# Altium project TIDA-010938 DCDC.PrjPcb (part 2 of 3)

## Sheet TIDA-010938 bidirectional DC-DC_Interleaved1.SchDoc
size 558 x 431 mm; Date: Not shown in title block; ApprovedBy: Not shown in title block; CheckedBy: Not shown in title block; Author: Not shown in title block; CompanyName: Not shown in title block; Engineer: Not shown in title block; Organization: Not shown in title block; Address1: Not shown in title block; Address2: Not shown in title block; Address3: Not shown in title block; Address4: Not shown in title block; DocumentNumber: 1; Revision: Use project parameter SCH_Rev; SheetNumber: 6; SheetTotal: 9; PageSetup: Record=PageOptions¦CenterHorizontal=True¦CenterVertical=True¦PrintScale=1.00¦XCorrection=1.00¦YCorrection=1.00¦PrintKind=0¦BorderSize=5000000¦LeftOffset=0¦BottomOffset=0¦Orientation=2¦PaperLength=1000¦PaperWidth=1000¦Scale=100¦PaperSource=15¦PrintQuality=600¦MediaType=1¦DitherType=10¦PaperKind=Letter¦PrintScaleMode=1
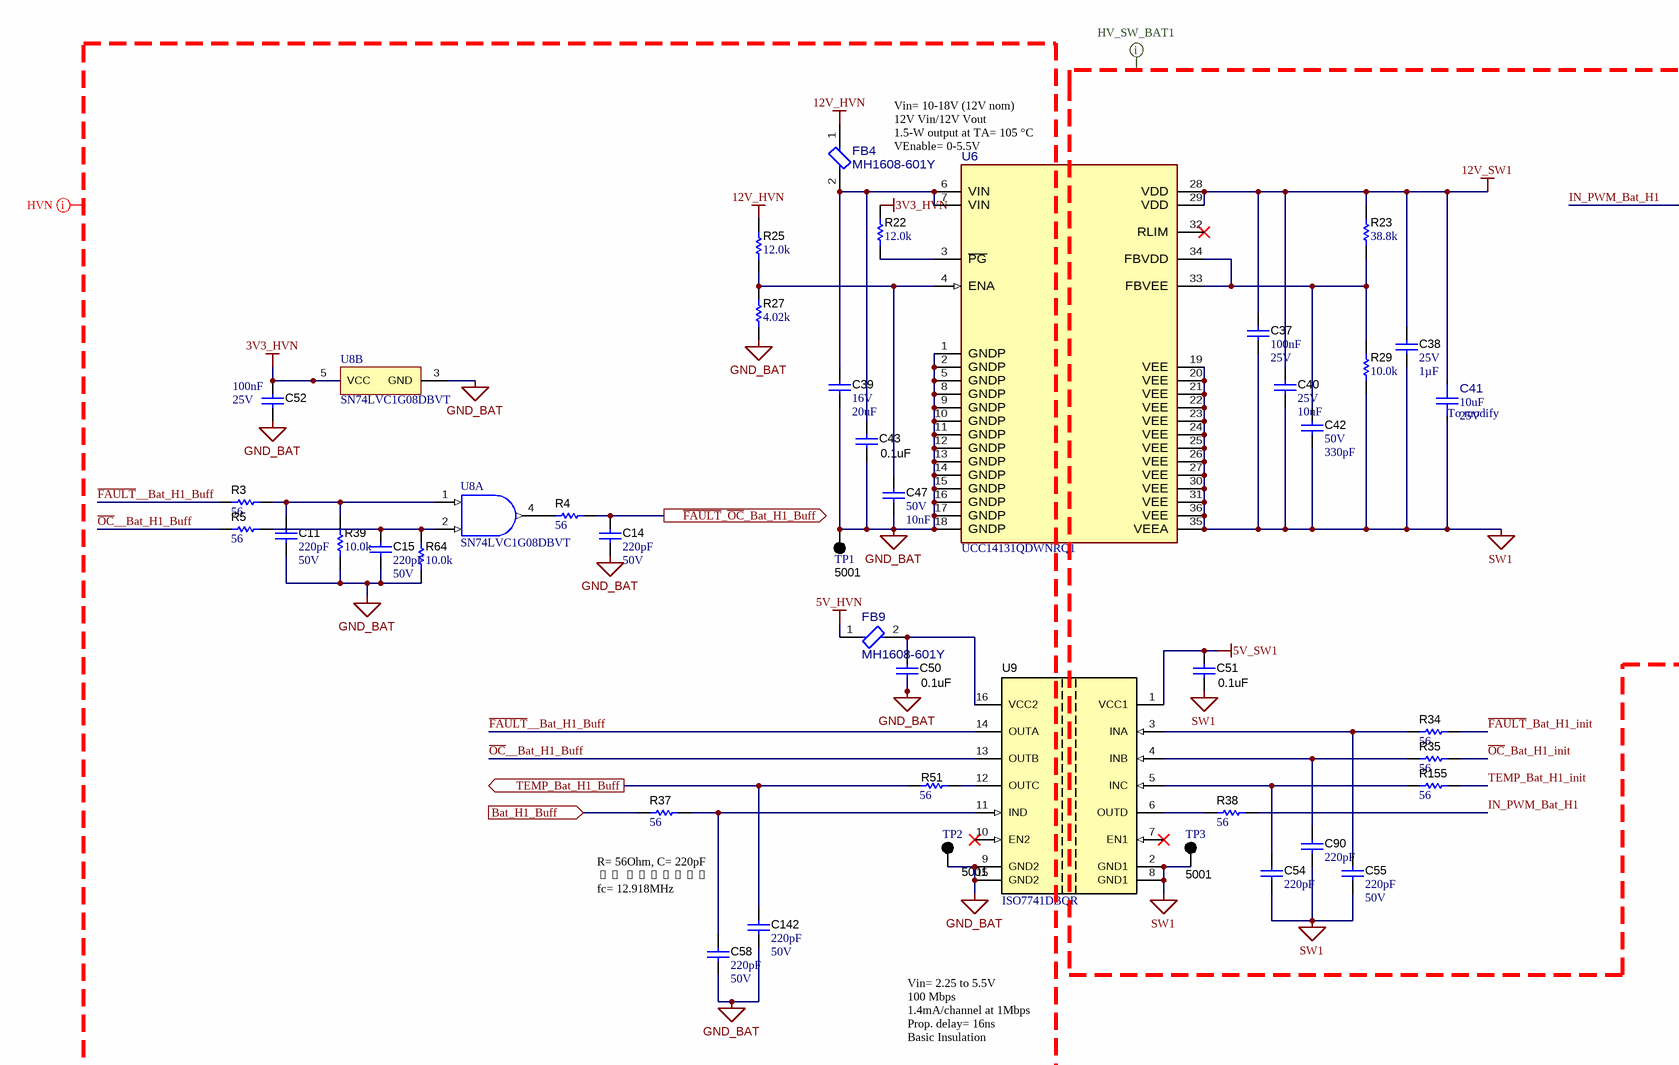
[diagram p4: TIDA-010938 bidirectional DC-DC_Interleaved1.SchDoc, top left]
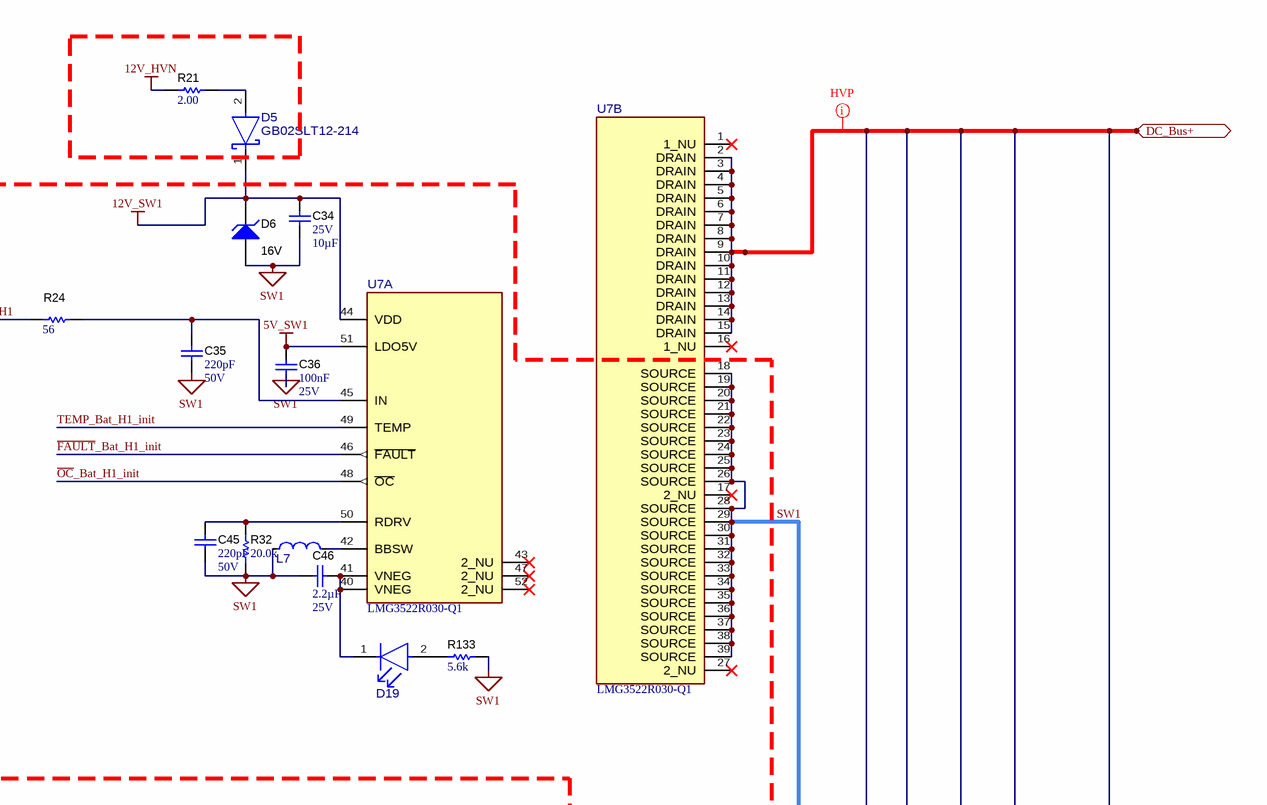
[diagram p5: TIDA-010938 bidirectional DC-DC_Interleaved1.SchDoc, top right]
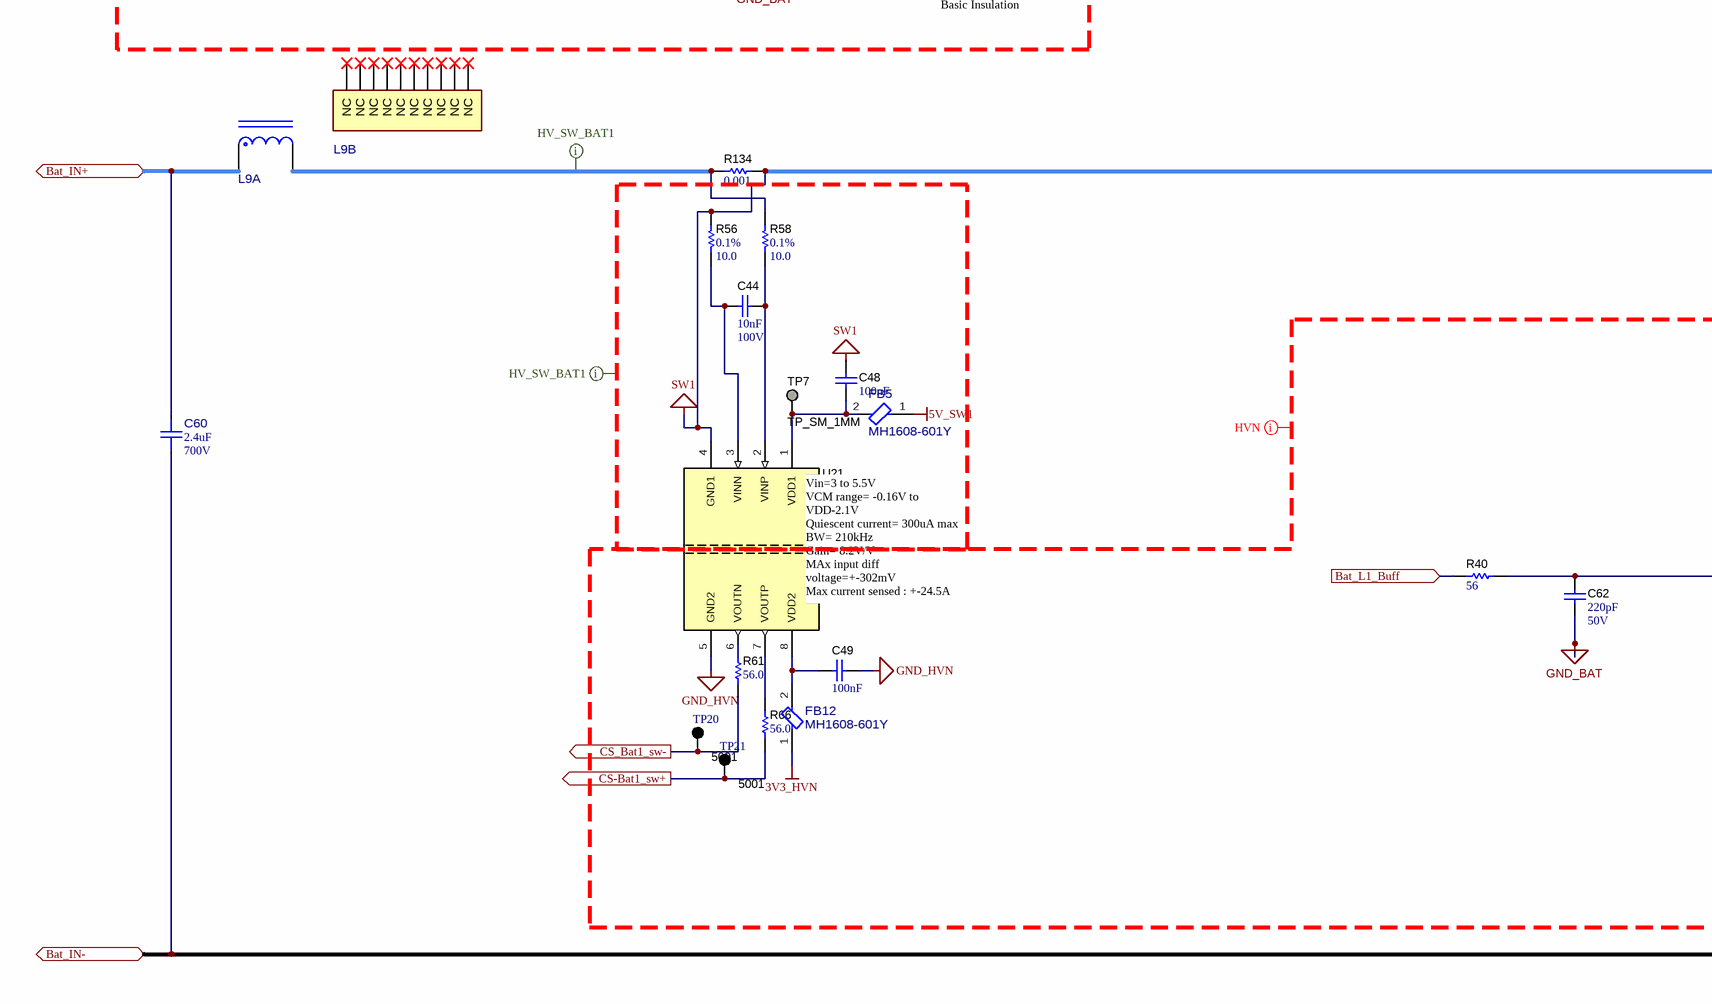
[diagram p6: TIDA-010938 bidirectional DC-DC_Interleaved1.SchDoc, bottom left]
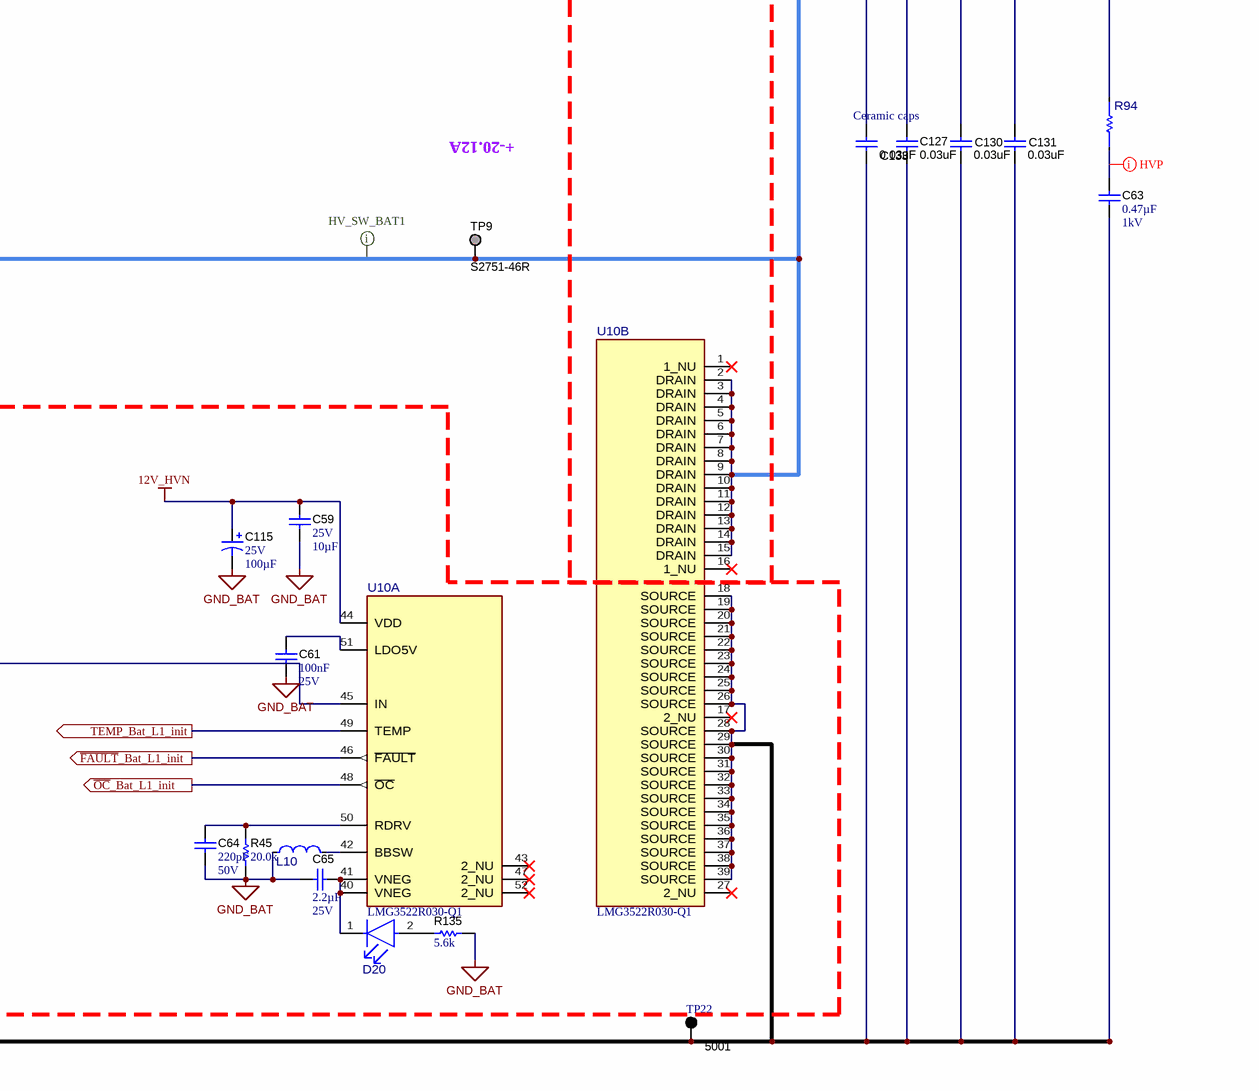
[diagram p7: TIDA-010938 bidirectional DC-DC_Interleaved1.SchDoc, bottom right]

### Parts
C11  Cap_F: 220pF  VDC_V: 50V  [0603]  (hidden comment: GRM188R71H221KA01D)
C14  Cap_F: 220pF  VDC_V: 50V  [0603]  (hidden comment: GRM188R71H221KA01D)
C15  Cap_F: 220pF  VDC_V: 50V  [0603]  (hidden comment: GRM188R71H221KA01D)
C34  VDC_V: 25V  ValueDisplayed: 10µF  [1206_180]  (hidden comment: TMK316AB7106KLHT)
C35  Cap_F: 220pF  VDC_V: 50V  [0603]  (hidden comment: GRM188R71H221KA01D)
C36  Cap_F: 100nF  VDC_V: 25V  [0603]  (hidden comment: 06033C104JAT2A)
C37  Cap_F: 100nF  VDC_V: 25V  [0603]  (hidden comment: 06033C104JAT2A)
C38  VDC_V: 25V  ValueDisplayed: 1µF  [0603]  (hidden comment: TMK107BJ105KA-T)
C39  VDC_V: 16V  ValueDisplayed: 20uF  [0704]  (hidden comment: GRMJN7R61C206ME05)
C40  VDC_V: 25V  ValueDisplayed: 10uF  [0603]  (hidden comment: TMK107BBJ106MA-T)
C41  ValueDisplayed: 10uF  VDC_V: 25V  [FP-ZRB18AR61E106ME01L_0603-MFG]  (hidden comment: ZRB18AR61E106ME01L)
C42  VDC_V: 50V  ValueDisplayed: 330pF  [0603]  (hidden comment: GRM1885C1H331JA01D)
C43  ValueDisplayed: 0.1uF  [0603]  (hidden comment: 885012206095)
C44  Cap_F: 10nF  VDC_V: 100V  [0603]  (hidden comment: CGA3E2X7R2A103K080AA)
C45  Cap_F: 220pF  VDC_V: 50V  [0603]  (hidden comment: GRM188R71H221KA01D)
C46  Cap_F: 2.2µF  VDC_V: 25V  [0805_HV]  (hidden comment: CGA4J3X7R1E225K125AB)
C47  VDC_V: 50V  Cap_F: 10nF  [0603]  (hidden comment: 885012206089)
C48  Cap_F: 100nF  [0603]  (hidden comment: 06033C104JAT2A)
C49  Cap_F: 100nF  [0603]  (hidden comment: 06033C104JAT2A)
C50  ValueDisplayed: 0.1uF  [0603]  (hidden comment: 885012206095)
C51  ValueDisplayed: 0.1uF  [0603]  (hidden comment: 885012206095)
C52  Cap_F: 100nF  VDC_V: 25V  [0603]  (hidden comment: 06033C104JAT2A)
C54  Cap_F: 220pF  [0603]  (hidden comment: GRM188R71H221KA01D)
C55  Cap_F: 220pF  VDC_V: 50V  [0603]  (hidden comment: GRM188R71H221KA01D)
C58  Cap_F: 220pF  VDC_V: 50V  [0603]  (hidden comment: GRM188R71H221KA01D)
C59  VDC_V: 25V  ValueDisplayed: 10µF  [1206_180]  (hidden comment: TMK316AB7106KLHT)
C60  ValueDisplayed: 2.4uF  VDC_V: 700V  [FP-C4AUJBU4240M1WJ_RADIAL-MFG]  (hidden comment: C4AUJBU4240M1WJ)
C61  Cap_F: 100nF  VDC_V: 25V  [0603]  (hidden comment: 06033C104JAT2A)
C62  Cap_F: 220pF  VDC_V: 50V  [0603]  (hidden comment: GRM188R71H221KA01D)
C63  ValueDisplayed: 0.47µF  VDC_V: 1kV  [2220]  (hidden comment: 2220Y1K00474KETWS2)
C64  Cap_F: 220pF  VDC_V: 50V  [0603]  (hidden comment: GRM188R71H221KA01D)
C65  Cap_F: 2.2µF  VDC_V: 25V  [0805_HV]  (hidden comment: CGA4J3X7R1E225K125AB)
C90  Cap_F: 220pF  [0603]  (hidden comment: GRM188R71H221KA01D)
C115  VDC_V: 25V  ValueDisplayed: 100µF  [UWT_630x770]  (hidden comment: UWT1E101MCL1GS)
C127  ValueDisplayed: 0.03uF  [1812_254]  (hidden comment: C1812C303KDGLCAUTO)
C130  ValueDisplayed: 0.03uF  [1812_254]  (hidden comment: C1812C303KDGLCAUTO)
C131  ValueDisplayed: 0.03uF  [1812_254]  (hidden comment: C1812C303KDGLCAUTO)
C133  ValueDisplayed: 0.03uF  [1812_254]  (hidden comment: C1812C303KDGLCAUTO)
C142  Cap_F: 220pF  VDC_V: 50V  [0603]  (hidden comment: GRM188R71H221KA01D)
D5  GB02SLT12-214  [FP-GB02SLT12-214_DO-214AA-MFG]
D6  value 16V  [SOD-123]  (hidden comment: BZT52C16-7-F)
D19  KG DELLS1.22-JGKH-24  [FP-KG DELLS1.22-JGKH-24_0603-MFG]  (value not drawn)
D20  KG DELLS1.22-JGKH-24  [FP-KG DELLS1.22-JGKH-24_0603-MFG]  (value not drawn)
FB4  MH1608-601Y  [FP-MH1608-601Y_0603-MFG]
FB5  MH1608-601Y  [FP-MH1608-601Y_0603-MFG]
FB9  MH1608-601Y  [FP-MH1608-601Y_0603-MFG]
FB12  MH1608-601Y  [FP-MH1608-601Y_0603-MFG]
L7  SDEM20161T-4R7MS  [FP-SDEM20161T-4R7MS_SMD2-MFG]  (value not drawn)
L9  B180975  [FP-B180975_PTH12_55MM5_50MM0-MFG]  (value not drawn)  (parts A,B of 2)
L10  SDEM20161T-4R7MS  [FP-SDEM20161T-4R7MS_SMD2-MFG]  (value not drawn)
R3  ValueDisplayed: 56  [0603]  (hidden comment: RG1608P-560-B-T5)
R4  ValueDisplayed: 56  [0603]  (hidden comment: RG1608P-560-B-T5)
R5  ValueDisplayed: 56  [0603]  (hidden comment: RG1608P-560-B-T5)
R21  ValueDisplayed: 2.00  [0603]  (hidden comment: RT0603DRE072RL)
R22  ValueDisplayed: 12.0k  [0603]  (hidden comment: ERJ-3EKF1202V)
R23  ValueDisplayed: 38.8k  [0603]  (hidden comment: RT0603DRE0738K8L)
R24  ValueDisplayed: 56  [0603]  (hidden comment: RG1608P-560-B-T5)
R25  ValueDisplayed: 12.0k  [0603]  (hidden comment: ERJ-3EKF1202V)
R27  ValueDisplayed: 4.02k  [0603]  (hidden comment: RT0603BRD074K02L)
R29  ValueDisplayed: 10.0k  [0603]  (hidden comment: RG1608P-103-B-T5)
R32  ValueDisplayed: 20.0k  [0603]  (hidden comment: RC0603FR-0720KL)
R34  ValueDisplayed: 56  [0603]  (hidden comment: RG1608P-560-B-T5)
R35  ValueDisplayed: 56  [0603]  (hidden comment: RG1608P-560-B-T5)
R37  ValueDisplayed: 56  [0603]  (hidden comment: RG1608P-560-B-T5)
R38  ValueDisplayed: 56  [0603]  (hidden comment: RG1608P-560-B-T5)
R39  ValueDisplayed: 10.0k  [0603]  (hidden comment: RG1608P-103-B-T5)
R40  ValueDisplayed: 56  [0603]  (hidden comment: RG1608P-560-B-T5)
R45  ValueDisplayed: 20.0k  [0603]  (hidden comment: RC0603FR-0720KL)
R51  ValueDisplayed: 56  [0603]  (hidden comment: RG1608P-560-B-T5)
R56  Tolerance_%: 0.1%  ValueDisplayed: 10.0  [0603]  (hidden comment: RT0603BRD0710RL)
R58  Tolerance_%: 0.1%  ValueDisplayed: 10.0  [0603]  (hidden comment: RT0603BRD0710RL)
R61  ValueDisplayed: 56.0  [0603]  (hidden comment: RC0603FR-0756RL)
R64  ValueDisplayed: 10.0k  [0603]  (hidden comment: RG1608P-103-B-T5)
R66  ValueDisplayed: 56.0  [0603]  (hidden comment: RC0603FR-0756RL)
R94  CSR0805FKR250  [FP-CSR0805FKR250_0805-MFG]  (value not drawn)
R133  ValueDisplayed: 5.6k  [0603]  (hidden comment: RC0603JR-075K6L)
R134  ValueDisplayed: 0.001  [CSS2H-2512_H077Y042]  (hidden comment: CSS2H-2512R-1L00F)
R135  ValueDisplayed: 5.6k  [0603]  (hidden comment: RC0603JR-075K6L)
R155  ValueDisplayed: 56  [0603]  (hidden comment: RG1608P-560-B-T5)
TP1  5001  [Keystone5001]
TP2  5001  [Keystone5001]
TP3  5001  [Keystone5001]
TP7  TP_SM_1MM  [TP_SM_1MM]  (no BOM)
TP9  S2751-46R  [Harwin_S2751-46R]  (no BOM)
TP20  5001  [Keystone5001]
TP21  5001  [Keystone5001]
TP22  5001  [Keystone5001]
U6  UCC14131QDWNRQ1  [DWJ0036A-MFG]
U7  LMG3522R030-Q1  [RQS0052C-C01-MFG]  (parts A,B of 2)
U8  SN74LVC1G08DBVT  [DBV0005A_N]  (parts A,B of 2)
U9  ISO7741DBQR  [DBQ0016A_N]
U10  LMG3522R030-Q1  [RQS0052C-C01-MFG]  (parts A,B of 2)
U21  AMC1302DWV  [DWV0008A]

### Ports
Bat_H1_Buff (in), Bat_IN+ (bidir), Bat_IN- (bidir), Bat_L1_Buff (in), CS-Bat1_sw+ (out), CS_Bat1_sw- (out), DC_Bus+ (bidir), TEMP_Bat_H1_Buff (out), TEMP_Bat_L1_init (out), ~{FAULT}_Bat_L1_init (out), ~{FAULT}_~{OC}_Bat_H1_Buff (out), ~{OC}_Bat_L1_init (out)

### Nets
3V3_HVN: C52.1 FB12.1 R22.1 U8.5(VCC)
5V_HVN: FB9.1
5V_SW1: C36.2 C51.1 FB5.1 U7.51(LDO5V) U9.1(VCC1)
12V_HVN: C59.1 C115.1(+) FB4.1 R21.1 R25.1 U10.44(VDD)
12V_SW1: C34.1 C37.2 C38.2 C40.2 C41.1 D5.1(CATHODE) D6.1(K) R23.1 U6.28(VDD) U6.29(VDD) U7.44(VDD)
DC_Bus-: C60.1 C63.2 C127.2 C130.2 C131.2 C133.2 TP22.1 U10.18(SOURCE) U10.19(SOURCE) U10.20(SOURCE) U10.21(SOURCE) U10.22(SOURCE) U10.23(SOURCE) U10.24(SOURCE) U10.25(SOURCE) U10.26(SOURCE) U10.28(SOURCE) U10.29(SOURCE) U10.30(SOURCE) U10.31(SOURCE) U10.32(SOURCE) U10.33(SOURCE) U10.34(SOURCE) U10.35(SOURCE) U10.36(SOURCE) U10.37(SOURCE) U10.38(SOURCE) U10.39(SOURCE) ; port Bat_IN-
GND_BAT: C11.1 C14.1 C15.1 C39.1 C43.2 C47.1 C50.2 C52.2 C58.1 C59.2 C61.1 C62.1 C64.1 C65.2 C115.2(-) C142.1 L10.1 R27.1 R39.1 R45.1 R64.1 R135.1 TP1.1 TP2.1 U6.1(GNDP) U6.2(GNDP) U6.5(GNDP) U6.8(GNDP) U6.9(GNDP) U6.10(GNDP) U6.11(GNDP) U6.12(GNDP) U6.13(GNDP) U6.14(GNDP) U6.15(GNDP) U6.16(GNDP) U6.17(GNDP) U6.18(GNDP) U8.3(GND) U9.9(GND2) U9.15(GND2)
GND_HVN: C49.2 U21.5(GND2)
SW1: C34.2 C35.1 C36.1 C37.1 C38.1 C40.1 C41.2 C42.2 C45.1 C46.2 C48.2 C51.2 C54.1 C55.1 C90.1 D6.2(A) L7.1 R29.2 R32.1 R56.1 R133.1 R134.2 TP3.1 TP9.1 U6.19(VEE) U6.20(VEE) U6.21(VEE) U6.22(VEE) U6.23(VEE) U6.24(VEE) U6.25(VEE) U6.26(VEE) U6.27(VEE) U6.30(VEE) U6.31(VEE) U6.35(VEEA) U6.36(VEE) U7.18(SOURCE) U7.19(SOURCE) U7.20(SOURCE) U7.21(SOURCE) U7.22(SOURCE) U7.23(SOURCE) U7.24(SOURCE) U7.25(SOURCE) U7.26(SOURCE) U7.28(SOURCE) U7.29(SOURCE) U7.30(SOURCE) U7.31(SOURCE) U7.32(SOURCE) U7.33(SOURCE) U7.34(SOURCE) U7.35(SOURCE) U7.36(SOURCE) U7.37(SOURCE) U7.38(SOURCE) U7.39(SOURCE) U9.2(GND1) U9.8(GND1) U10.2(DRAIN) U10.3(DRAIN) U10.4(DRAIN) U10.5(DRAIN) U10.6(DRAIN) U10.7(DRAIN) U10.8(DRAIN) U10.9(DRAIN) U10.10(DRAIN) U10.11(DRAIN) U10.12(DRAIN) U10.13(DRAIN) U10.14(DRAIN) U10.15(DRAIN) U21.4(GND1)
Bat_H1_Buff: R37.1 ; port Bat_H1_Buff
Bat_IN+: C60.2 L9.1 ; port Bat_IN+
Bat_L1_Buff: R40.1 ; port Bat_L1_Buff
CS-Bat1_sw+: R66.1 TP21.1 ; port CS-Bat1_sw+
CS_Bat1_sw-: R61.1 TP20.1 ; port CS_Bat1_sw-
DC_Bus+: C127.1 C130.1 C131.1 C133.1 R94.2 U7.2(DRAIN) U7.3(DRAIN) U7.4(DRAIN) U7.5(DRAIN) U7.6(DRAIN) U7.7(DRAIN) U7.8(DRAIN) U7.9(DRAIN) U7.10(DRAIN) U7.11(DRAIN) U7.12(DRAIN) U7.13(DRAIN) U7.14(DRAIN) U7.15(DRAIN) ; port DC_Bus+
~{FAULT}__Bat_H1_Buff: R3.1 U9.14(OUTA)
~{FAULT}_Bat_H1_init: R34.2 U7.46(~{FAULT})
~{FAULT}_Bat_L1_init: U10.46(~{FAULT}) ; port ~{FAULT}_Bat_L1_init
~{FAULT}_~{OC}_Bat_H1_Buff: C14.2 R4.2 ; port ~{FAULT}_~{OC}_Bat_H1_Buff
IN_PWM_Bat_H1: R24.1 R38.2
~{OC}__Bat_H1_Buff: R5.1 U9.13(OUTB)
~{OC}_Bat_H1_init: R35.2 U7.48(~{OC})
~{OC}_Bat_L1_init: U10.48(~{OC}) ; port ~{OC}_Bat_L1_init
TEMP_Bat_H1_Buff: C142.2 R51.1 ; port TEMP_Bat_H1_Buff
TEMP_Bat_H1_init: R155.2 U7.49(TEMP)
TEMP_Bat_L1_init: U10.49(TEMP) ; port TEMP_Bat_L1_init
NetC11_2: C11.2 R3.2 R39.2 U8.1(A)
NetC15_2: C15.2 R5.2 R64.2 U8.2(B)
NetC35_2: C35.2 R24.2 U7.45(IN)
NetC39_2: C39.2 C43.1 FB4.2 U6.6(VIN) U6.7(VIN)
NetC42_1: C42.1 R23.2 R29.1 U6.33(FBVEE) U6.34(FBVDD)
NetC44_1: C44.1 R58.2 U21.2(VINP)
NetC44_2: C44.2 R56.2 U21.3(VINN)
NetC45_2: C45.2 R32.2 U7.50(RDRV)
NetC46_1: C46.1 D19.1(CATHODE) U7.40(VNEG) U7.41(VNEG)
NetC47_2: C47.2 R25.2 R27.2 U6.4(ENA)
NetC48_1: C48.1 FB5.2 TP7.1 U21.1(VDD1)
NetC49_1: C49.1 FB12.2 U21.8(VDD2)
NetC50_1: C50.1 FB9.2 U9.16(VCC2)
NetC54_2: C54.2 R155.1 U9.5(INC)
NetC55_2: C55.2 R34.1 U9.3(INA)
NetC58_2: C58.2 R37.2 U9.11(IND)
NetC61_2: C61.2 U10.51(LDO5V)
NetC62_2: C62.2 R40.2 U10.45(IN)
NetC63_1: C63.1 R94.1
NetC64_2: C64.2 R45.2 U10.50(RDRV)
NetC65_1: C65.1 D20.1(CATHODE) U10.40(VNEG) U10.41(VNEG)
NetC90_2: C90.2 R35.1 U9.4(INB)
NetD5_2: D5.2(ANODE) R21.2
NetD19_2: D19.2(ANODE) R133.2
NetD20_2: D20.2(ANODE) R135.2
NetL7_2: L7.2 U7.42(BBSW)
NetL9_6: L9.6 R58.1 R134.1
NetL10_2: L10.2 U10.42(BBSW)
NetR4_1: R4.1 U8.4(Y)
NetR22_2: R22.2 U6.3(~{PG})
NetR38_1: R38.1 U9.6(OUTD)
NetR51_2: R51.2 U9.12(OUTC)
NetR61_2: R61.2 U21.6(VOUTN)
NetR66_2: R66.2 U21.7(VOUTP)

Not connected (* = marked no-connect by the designer): L9 2(NC)* 3(NC)* 4(NC)* 5(NC)* 7(NC)* 8(NC)* 9(NC)* 10(NC)* 11(NC)* 12(NC)*; U6 32(RLIM)*; U7 1(1_NU)* 16(1_NU)* 17(2_NU)* 27(2_NU)* 43(2_NU)* 47(2_NU)* 52(2_NU)*; U9 7(EN1)* 10(EN2)*; U10 1(1_NU)* 16(1_NU)* 17(2_NU)* 27(2_NU)* 43(2_NU)* 47(2_NU)* 52(2_NU)*

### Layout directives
net class HVN: 3V3_HVN, 5V_HVN, 5V_SW1, 12V_HVN, 12V_SW1, GND_BAT, IN_PWM_Bat_H1, SW1, TEMP_Bat_H1_init, ~{FAULT}__Bat_H1_Buff, ~{FAULT}_Bat_H1_init, ~{OC}__Bat_H1_Buff, ~{OC}_Bat_H1_init
net class HV_SW_BAT1: 3V3_HVN, 5V_SW1, 12V_HVN, 12V_SW1, GND_BAT, GND_HVN, IN_PWM_Bat_H1, NetL9_6, SW1, TEMP_Bat_H1_init, ~{FAULT}_Bat_H1_init, ~{OC}_Bat_H1_init
net class HVP: DC_Bus+, NetC63_1

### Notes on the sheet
- Vin= 10-18V (12V nom)
  12V Vin/12V Vout
  1.5-W output at TA= 105 °C
  VEnable= 0-5.5V
- (near C41) To modify
- R= 56Ohm, C= 220pF
  𝜏= 1.23e-8
  fc= 12.918MHz
- Vin= 2.25 to 5.5V
  100 Mbps
  1.4mA/channel at 1Mbps
  Prop. delay= 16ns
  Basic Insulation
- +-20.12A
- Ceramic caps
- (near U21) 9 mA @ 5V
- (near U21) Vin=3 to 5.5V
  VCM range= -0.16V to VDD-2.1V
  Quiescent current= 300uA max
  BW= 210kHz
  Gain= 8.2V/V
  MAx input diff voltage=+-302mV
  Max current sensed : +-24.5A
- (near U21) 10 mA @ 5V

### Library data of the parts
C11 C14 C15 C35 C45 C55 C58 C62 C64 C142 = CMP-0007442-5: CAP, CERM, 220 pF, 50 V, +/- 10%, X7R, 0603; Manufacturer: MuRata; TaMin_C: -55°C; Polarized: N; SizeAreaWB_mm2: 4.68; Value1: Unknown; U/M: EA; Value: 220pF; TaMax_C: 125°C; SizeZ_mm: 1; SizeX_mm: 1.6; SizeY_mm: 0.8; SizeArea_mm2: 1.28; AEC Category: Q200
C34 C59 = CMP-0750154-1: CAP, CERM, 10 µF, 25 V,+/- 10%, X7R, AEC-Q200 Grade 1, 1206; Manufacturer: Taiyo Yuden; AEC Qualified: Y; SizeZ_mm: 1.8; TaMax_C: 125°C; TaMin_C: -55°C; Cap_Case: 1206; Polarized: N; AEC Grade: 1; SizeY_mm: 1.6; Value: 10uF; SizeX_mm: 3.2; SizeAreaWB_mm2: 10.92; AEC Category: Q200; U/M: EA; SizeArea_mm2: 5.12
C36 C37 C52 C61 = CMP-0006752-5: CAP, CERM, 0.1 uF, 25 V, +/- 5%, X7R, 0603; Manufacturer: AVX; TaMin_C: -55°C; ESR_ohm: 0.05; Polarized: N; SizeAreaWB_mm2: 4.68; Value1: 0.05 ohm; U/M: EA; Value: 0.1uF; TaMax_C: 125°C; SizeZ_mm: 1; SizeX_mm: 1.6; SizeY_mm: 0.8; SizeArea_mm2: 1.28; AEC Category: Q200
C38 = CMP-0086152-1: CAP, CERM, 1 µF, 25 V,+/- 10%, X5R, 0603; Manufacturer: Taiyo Yuden; SizeAreaWB_mm2: 4.68; SizeZ_mm: 1; U/M: EA; Green_REACh: Passed; Value: 1uF; AEC Qualified: N; TaMax_C: 85°C; Green_Lifecycle: Active; AEC Category: Q200; SizeArea_mm2: 1.28; TaMin_C: -55°C; SizeY_mm: 0.8; SizeX_mm: 1.6
C39 = CMP-0009474-2: CAP, CERM, 20 uF, 16 V, +/- 20%, X5R, 0704; Manufacturer: MuRata; TaMin_C: -55°C; Polarized: N; SizeAreaWB_mm2: 5.6; Value1: Unknown; U/M: EA; Value: 20uF; TaMax_C: 85°C; SizeZ_mm: 0.8; SizeX_mm: 1; SizeY_mm: 1.8; Cap_F: 20µF; AEC Category: Q200
C40 = CMP-0007507-5: CAP, CERM, 10 uF, 25 V, +/- 20%, X5R, 0603; Manufacturer: Taiyo Yuden; TaMin_C: -55°C; Polarized: N; SizeAreaWB_mm2: 4.68; Value1: Unknown; U/M: EA; Value: 10uF; TaMax_C: 85°C; SizeZ_mm: 1; SizeX_mm: 1.6; SizeY_mm: 0.8; SizeArea_mm2: 1.28; Cap_F: 10µF; AEC Category: Q200
C41 = CMP-0094458-1: 10µF ±20% 25V Ceramic Capacitor X5R 0603 (1608 Metric); Manufacturer: Murata Electronics; SizeZ_mm: 1.2mm; AEC Qualified: No
C42 = CMP-0007209-4: CAP, CERM, 330 pF, 50 V, +/- 5%, C0G/NP0, 0603; Manufacturer: MuRata; TaMin_C: -55°C; Polarized: N; SizeAreaWB_mm2: 4.68; Value1: Unknown; U/M: EA; Value: 330pF; TaMax_C: 125°C; SizeZ_mm: 1; SizeX_mm: 1.6; SizeY_mm: 0.8; SizeArea_mm2: 1.28; AEC Category: Q200
C43 C50 C51 = CMP-0006837-4: CAP, CERM, 0.1 uF, 50 V, +/- 10%, X7R, 0603; Manufacturer: Wurth Elektronik; TaMin_C: -55°C; Polarized: N; SizeAreaWB_mm2: 4.68; Value1: Unknown; U/M: EA; Value: 0.1uF; TaMax_C: 125°C; SizeZ_mm: 1; SizeX_mm: 1.6; SizeY_mm: 0.8; Value2: 50V; SizeArea_mm2: 1.28; CompType: Capacitor; Cap_F: 100nF; AEC Category: Q200
C44 = CMP-0007082-4: CAP, CERM, 0.01 uF, 100 V, +/- 10%, X7R, AEC-Q200 Grade 1, 0603; Manufacturer: TDK; TaMin_C: -55°C; ESR_ohm: 2.35428d; Polarized: N; SizeAreaWB_mm2: 4.68; Value1: 0.235428 ohm; U/M: EA; Value: 0.01uF; TaMax_C: 125°C; SizeZ_mm: 1; SizeX_mm: 1.6; SizeY_mm: 0.8; SizeArea_mm2: 1.28; AEC Qualified: Y; IRMS_A: 3.96995dA; AEC Category: Q200
C46 C65 = CMP-0007975-2: CAP, CERM, 2.2 uF, 25 V, +/- 10%, X7R, AEC-Q200 Grade 1, 0805; Manufacturer: TDK; TaMin_C: -55°C; Polarized: N; SizeAreaWB_mm2: 6.75; Value1: Unknown; U/M: EA; Value: 2.2uF; TaMax_C: 125°C; SizeZ_mm: 1.45; SizeX_mm: 2; SizeY_mm: 1.25; Cap_Case: 0805; SizeArea_mm2: 2.5; AEC Qualified: Y; AEC Grade: 1; AEC Category: Q200
C47 = CMP-0750039-1: CAP, CERM, 0.01 µF, 50 V,+/- 10%, X7R, 0603; Manufacturer: Wurth Elektronik; Polarized: N; AEC Category: Q200; TaMax_C: 125°C; SizeAreaWB_mm2: 4.68; Value: 0.01uF; SizeArea_mm2: 1.28; SizeY_mm: 0.8; SizeZ_mm: 1; ValueDisplayed: 0.01µF; SizeX_mm: 1.6; U/M: EA; TaMin_C: -55°C
C48 C49 = CMP-0006752-5: CAP, CERM, 0.1 uF, 25 V, +/- 5%, X7R, 0603; Manufacturer: AVX; TaMin_C: -55°C; ESR_ohm: 0.05; Polarized: N; SizeAreaWB_mm2: 4.68; Value1: 0.05 ohm; U/M: EA; Value: 0.1uF; TaMax_C: 125°C; SizeZ_mm: 1; SizeX_mm: 1.6; SizeY_mm: 0.8; Value2: 25V; SizeArea_mm2: 1.28; AEC Category: Q200
C54 C90 = CMP-0007442-5: CAP, CERM, 220 pF, 50 V, +/- 10%, X7R, 0603; Manufacturer: MuRata; TaMin_C: -55°C; Polarized: N; SizeAreaWB_mm2: 4.68; Value1: Unknown; U/M: EA; Value: 220pF; TaMax_C: 125°C; SizeZ_mm: 1; SizeX_mm: 1.6; SizeY_mm: 0.8; Value2: 50V; SizeArea_mm2: 1.28; AEC Category: Q200
C60 = CMP-0045063-1: 2.4 µF Film Capacitor 700V Polypropylene (PP), Metallized Radial; Manufacturer: KEMET; AEC Grade: Grade 2; AEC Qualified: Yes; Cap_F: 2.4µF; SizeZ_mm: 20.7mm; Tolerance_%: 5%; Value: 2.4µF
C63 = CMP-0086177-1: CAP, CERM, 0.47 µF, 1000 V,+/- 10%, X7R, AEC-Q200 Grade 1, 2220; Manufacturer: Knowles Capacitors; SizeAreaWB_mm2: 53.9; AEC Category: Q200; TaMax_C: 125°C; SizeArea_mm2: 28.5; SizeX_mm: 5.7; SizeZ_mm: 1.35; Value: 0.47uF; AEC Qualified: Y; TaMin_C: -55°C; SizeY_mm: 5; Value2: 1000V; AEC Grade: 1; U/M: EA; Cap_F: 470nF; Polarized: N
C115 = CMP-0081462-1: CAP, AL, 100 µF, 25 V, +/- 20%, SMD; Manufacturer: Nichicon; TaMin_C: -55°C; Polarized: Y; SizeAreaWB_mm2: 77.4; U/M: EA; Value: 100uF; TaMax_C: 105°C; SizeZ_mm: 8; SizeX_mm: 7; SizeY_mm: 6.6; Cap_Case: 6.3x7.7mm; SizeArea_mm2: 46.2; CompType: Capacitor; AEC Qualified: N; IRMS_A: 91mA; AEC Category: Q200
C127 C130 C131 C133 = CMP-0009326-2: 0.03 µF ±10% 1000V (1kV) Ceramic Capacitor C0G, NP0 1812 (4532 Metric); Manufacturer: Kemet; Polarized: N; Value: 0.03uF; U/M: EA; Cap_F: 30nF; Value1: Unknown; TaMin_C: -55°C; TaMax_C: 125°C; Cap_Case: 1812; AEC Category: Q200; SizeArea_mm2: 14.4; SizeAreaWB_mm2: 23.1; SizeX_mm: 4.5; SizeY_mm: 3.2; SizeZ_mm: 2.54
D5 = CMP-0095009-1: Diode Silicon Carbide Schottky 1200 V 2A (DC) Surface Mount DO-214AA; Manufacturer: GeneSiC Semiconductor; Max Surge Forward Current: 20A; ValueDisplayed: 122pF; Vf_V: 1.2kV; Peak Reverse Current: 1uA; SizeZ_mm: 2.44mm; AEC Qualified: No; TJmax_C: 175°C
D6 = CMP-0005769-4: Diode, Zener, 16 V, 500 mW, AEC-Q101, SOD-123; Manufacturer: Diodes Inc.; SizeZ_mm: 1.35; AEC Qualified: Y; SizeX_mm: 3.85; AEC Category: Q101; Power_W: 500mW; SizeY_mm: 1.7; Value1: 0.5W; SizeAreaWB_mm2: 13.095; SizeArea_mm2: 6.545; RJA_CperW: 338
D19 D20 = CMP-0093310-1: Standard LEDs - SMD Green TOPLED E 1608; Manufacturer: Osram Opto; AEC Grade: Grade 2; LambdaP: 572nm; SizeZ_mm: 0.7mm; LuminousFlux_PhiV: 0.016-0.0295lm; Luminous Intensity: 4.5-9.7mcd; LambdaD: 570nm; Tjmax_C: 125°C; Angle: 120°; Led Orientation: Top View; Forward Current: 2mA; Vf_V: 1.8V; AEC Qualified: Yes; Vr_V: 12V
FB4 FB5 FB9 FB12 = CMP-0037505-1: 600 Ohms @ 100 MHz 1 Power, Signal Line Ferrite Bead 0603 (1608 Metric) 1A 200mOhm; Manufacturer: Bourns; DCR_ohm: 0.2; SizeZ_mm: 1mm; AEC Qualified: No; Impedance At Frequency: 600Ω @ 100MHz; Test Frequency: 100MHz; Tolerance_%: 25%
L7 L10 = CMP-0089347-1: 4.7µH Unshielded Inductor 1.1A 426mOhm Max 0806 (2016 Metric); Manufacturer: Cyntec; AEC Qualified: No; Material: Metal Dust; Isat: 1.26A; Test Frequency: 1MHz; DCR_ohm: 0.426; SizeZ_mm: 1mm; Tolerance_%: 20%
L9 = CMP-0048784-1: Bi-directional DC-DC Inductor 186.7µH ± 10%; Manufacturer: Bourns; AEC Qualified: No; SizeZ_mm: 45mm; Value: 186.7uH; Test Frequency: 100kHz
R3-R5 R24 R34 R35 R37 R38 R40 R51 R155 = CMP-0023572-3: RES, 56, 0.1%, 0.1 W, 0603; Manufacturer: Susumu Co Ltd; Power_W: 100mW; TempCo: 25 ppm/C; Value_Code: 56R0; U/M: EA; Value: 56; SizeX_mm: 1.6; SizeY_mm: 0.8; SizeZ_mm: 1; Value2: 0.1W; SizeArea_mm2: 1.28; VDC_V: 75V; AEC Category: Q200
R21 = CMP-0025114-2: RES, 2.00, 0.5%, 0.1 W, 0603; Manufacturer: Yageo America; Power_W: 100mW; TempCo: 50 ppm/C; Value_Code: 2R00; U/M: EA; Value: 2.00; EIA_Code: E192; Res_ohm: 2; SizeX_mm: 1.6; SizeY_mm: 0.8; SizeZ_mm: 1; Value2: 0.1W; SizeArea_mm2: 1.28; VDC_V: 75V; AEC Category: Q200
R22 R25 = CMP-0022685-3: RES, 12.0 k, 1%, 0.1 W, 0603; Manufacturer: Panasonic; Power_W: 100mW; TempCo: 100 ppm/C; Value_Code: 12k0; U/M: EA; Value: 12.0k; Res_ohm: 12k; SizeX_mm: 1.6; SizeY_mm: 0.8; SizeZ_mm: 1; Value2: 0.1W; SizeArea_mm2: 1.28; VDC_V: 75V; AEC Category: Q200
R23 = CMP-0025200-2: RES, 38.8 k, 0.5%, 0.1 W, 0603; Manufacturer: Yageo America; Power_W: 100mW; TempCo: 50 ppm/C; Value_Code: 38k8; U/M: EA; Value: 38.8k; EIA_Code: E192; SizeX_mm: 1.6; SizeY_mm: 0.8; SizeZ_mm: 1; Value2: 0.1W; SizeArea_mm2: 1.28; VDC_V: 75V; AEC Category: Q200
R27 = CMP-0024286-2: RES, 4.02 k, 0.1%, 0.1 W, 0603; Manufacturer: Yageo America; Power_W: 100mW; TempCo: 25 ppm/C; Value_Code: 4k02; U/M: EA; Value: 4.02k; EIA_Code: E192; SizeX_mm: 1.6; SizeY_mm: 0.8; SizeZ_mm: 1; Value2: 0.1W; SizeArea_mm2: 1.28; VDC_V: 75V; AEC Category: Q200
R29 = CMP-0023404-1: RES, 10.0 k, 0.1%, 0.1 W, 0603; Manufacturer: Susumu Co Ltd; Power_W: 100mW; TempCo: 25 ppm/C; Value_Code: 10k0; U/M: EA; Value: 10.0k; EIA_Code: E192; Res_ohm: 10k; SizeX_mm: 1.6; SizeY_mm: 0.8; SizeZ_mm: 1; Value2: 0.1W; SizeArea_mm2: 1.28; VDC_V: 75V; AEC Category: Q200
R32 R45 = CMP-0022906-5: RES, 20.0 k, 1%, 0.1 W, 0603; Manufacturer: Yageo; Power_W: 100mW; TempCo: 100 ppm/C; Value_Code: 20k0; Value: 20.0k; EIA_Code: E96; Res_ohm: 20k; SizeX_mm: 1.6; SizeY_mm: 0.8; SizeZ_mm: 1; Value2: 0.1W; SizeArea_mm2: 1.28; AEC Qualified: N; VDC_V: 75V; AEC Category: Q200; SizeAreaWB_mm2: 4.68
R39 R64 = CMP-0023404-3: RES, 10.0 k, 0.1%, 0.1 W, 0603; Manufacturer: Susumu Co Ltd; Power_W: 100mW; TempCo: 25 ppm/C; Value_Code: 10k0; U/M: EA; Value: 10.0k; EIA_Code: E192; Res_ohm: 10k; SizeX_mm: 1.6; SizeY_mm: 0.8; SizeZ_mm: 1; Value2: 0.1W; SizeArea_mm2: 1.28; VDC_V: 75V; AEC Category: Q200
R56 R58 = CMP-0023661-3: RES, 10.0, 0.1%, 0.1 W, 0603; Manufacturer: Yageo America; Power_W: 100mW; TempCo: 25 ppm/C; Value_Code: 10R0; U/M: EA; Value: 10.0; EIA_Code: E192; Res_ohm: 10; SizeX_mm: 1.6; SizeY_mm: 0.8; SizeZ_mm: 1; Value2: 0.1W; SizeArea_mm2: 1.28; VDC_V: 75V; AEC Category: Q200
R61 R66 = CMP-0023188-5: RES, 56.0, 1%, 0.1 W, 0603; Manufacturer: Yageo; Power_W: 100mW; TempCo: 100 ppm/C; Value_Code: 56R0; Value: 56.0; Res_ohm: 56; SizeX_mm: 1.6; SizeY_mm: 0.8; SizeZ_mm: 1; Value2: 0.1W; SizeArea_mm2: 1.28; AEC Qualified: N; VDC_V: 75V; AEC Category: Q200; SizeAreaWB_mm2: 4.68
R94 = CMP-0088568-2: 250 mOhms ±1% 0.25W, 1/4W Chip Resistor 0805 (2012 Metric) Current Sense Thick Film; Manufacturer: Stackpole Electronics Inc; TempCo: 200ppm/°C; Res_ohm: 0.25; Power_W: 250mW; SizeZ_mm: 0.65mm; AEC Qualified: No
R133 R135 = CMP-0025933-5: RES, 5.6 k, 5%, 0.1 W, 0603; Manufacturer: Yageo; Power_W: 100mW; TempCo: 100 ppm/C; Value_Code: 5k60; Value: 5.6k; EIA_Code: E24; SizeX_mm: 1.6; SizeY_mm: 0.8; SizeZ_mm: 1; Value2: 0.1W; SizeArea_mm2: 1.28; AEC Qualified: N; VDC_V: 75V; AEC Category: Q200; SizeAreaWB_mm2: 4.68
R134 = CMP-0084746-1: RES, 0.001, 1%, 5 W, AEC-Q200 Grade 0, 6.35x3.05mm; Manufacturer: Bourns; SizeAreaWB_mm2: 42.1675; SizeArea_mm2: 19.3675; SizeY_mm: 3.05; SizeX_mm: 6.35; AEC Grade: 0; EIA_Code: E96; Value: 0.001; Res_ohm: 1m; Power_W: 5W; SizeZ_mm: 0.87; TempCo: 75 ppm/C; Value_Code: 1L000; AEC Qualified: Y; AEC Category: Q200
TP1-TP3 TP20-TP22 = CMP-0055138-2: Test Point, Miniature, Black, TH; Manufacturer: Keystone Electronics; ContactFinish: Silver; CNHeader: FALSE; Green_Lifecycle: Active; Green_REACh: Passed; CT: TRUE
TP7 = CMP-0003825-1: 1mm Test Point, SMT; Manufacturer: Any
TP9 = CMP-0003968-1: Test Point, SMT; Manufacturer: Harwin
U6 = CMP-0033793-2: Automotive 1.5-W, 12-V VIN / 12-VOUT, 15-V VIN / 15-V VOUT, HighDensity, > 5-kVRMS, Isolated DC/DC Module; Manufacturer: Texas Instruments; SizeZ_mm: 3.55mm; AEC Qualified: Yes; AEC Grade: Grade 1; Max Supply Voltage: 18V; Min Supply Voltage: 9V; Nominal Supply Current: 200-270mA; Number Of Outputs: 2; Output Type: AdjustableProgrammable; Output Voltage: 10-18V; Standoff Height: 0.1mm; Switching Frequency: 18MHz; TaMax_C: +125°C; TaMin_C: -40°C; TJmax_C: +150°C; AEC Category: Q200; CompType: IC
U7 U10 = CMP-0094891-1: 650-V 30-mΩ GaN FET with Integrated Driver, Protection, and Temperature Reporting; Manufacturer: Texas Instruments; Max Supply Voltage: 18V; TaMax_C: +125°C; TaMin_C: -40°C; Nominal Supply Current: 16mA; Number Of Outputs: 1; Standoff Height: 0mm; Min Supply Voltage: 7.5V; TJmax_C: +150°C; AEC Grade: Grade 1; SizeZ_mm: 1mm; Output Voltage: 520V; AEC Qualified: Yes
U8 = CMP-0051571-2: Single 2-Input Positive-AND Gate, DBV0005A, SMALL T&R; Manufacturer: Texas Instruments; Voltage(Nom)(V): 1.8,2.5,3.3,5; Bits(#): 1; Rating: Catalog; F @ Nom Voltage(Max)(Mhz): 150; 3-State Output: No; Gate Type: AND; Output Drive (IOL/IOH)(Max)(mA): 32/-32; Technology Family: LVC; Logic: True; VCC(Max)(V): 5.5; ICC @ Nom Voltage(Max)(mA): 0.01; VCC(Min)(V): 1.65; tpd @ Nom Voltage(Max)(ns): 4.5,6,4,5; Input Type: CMOS/TTL; Output Type: CMOS; AEC Category: Q200; AEC Qualified: N; CompType: IC
U9 = CMP-0013040-3: High Speed, Robust EMC Quad-Channel Digital Isolators, DBQ0016A (SSOP-16); Manufacturer: Texas Instruments; SizeX_mm: 6; SizeY_mm: 10; CompType: IC; SizeZ_mm: 1.75; SizeArea_mm2: 60; SizeAreaWB_mm2: 96; AEC Category: Q200; AEC Qualified: N
U21 = CMP-0080671-1: Precision Reinforced Isolated Amplifier for Current Sensing, DWV0008A (SOIC-8); Alternate PartNumber: AMC1302DWVR; Alternate Manufacturer: Texas Instruments; SizeAreaWB_mm2: 105.975; SizeZ_mm: 2.8; SizeX_mm: 11.5; SizeY_mm: 5.85; SizeArea_mm2: 67.275; CompType: IC; AEC Qualified: N; AEC Category: Q200

## Sheet TIDA-010938 DC-DC_VoltageMeasurement.SchDoc
size 431 x 279 mm; Date: Not shown in title block; ApprovedBy: Not shown in title block; CheckedBy: Not shown in title block; Author: Not shown in title block; CompanyName: Not shown in title block; Engineer: Not shown in title block; Organization: Not shown in title block; Address1: Not shown in title block; Address2: Not shown in title block; Address3: Not shown in title block; Address4: Not shown in title block; DocumentNumber: 1; Revision: Use project parameter SCH_Rev; SheetNumber: 9; SheetTotal: 9; PageSetup: Record=PageOptions¦CenterHorizontal=True¦CenterVertical=True¦PrintScale=1.00¦XCorrection=1.00¦YCorrection=1.00¦PrintKind=0¦BorderSize=5000000¦LeftOffset=0¦BottomOffset=0¦Orientation=2¦PaperLength=1000¦PaperWidth=1000¦Scale=100¦PaperSource=15¦PrintQuality=600¦MediaType=1¦DitherType=10¦PaperKind=Letter¦PrintScaleMode=1
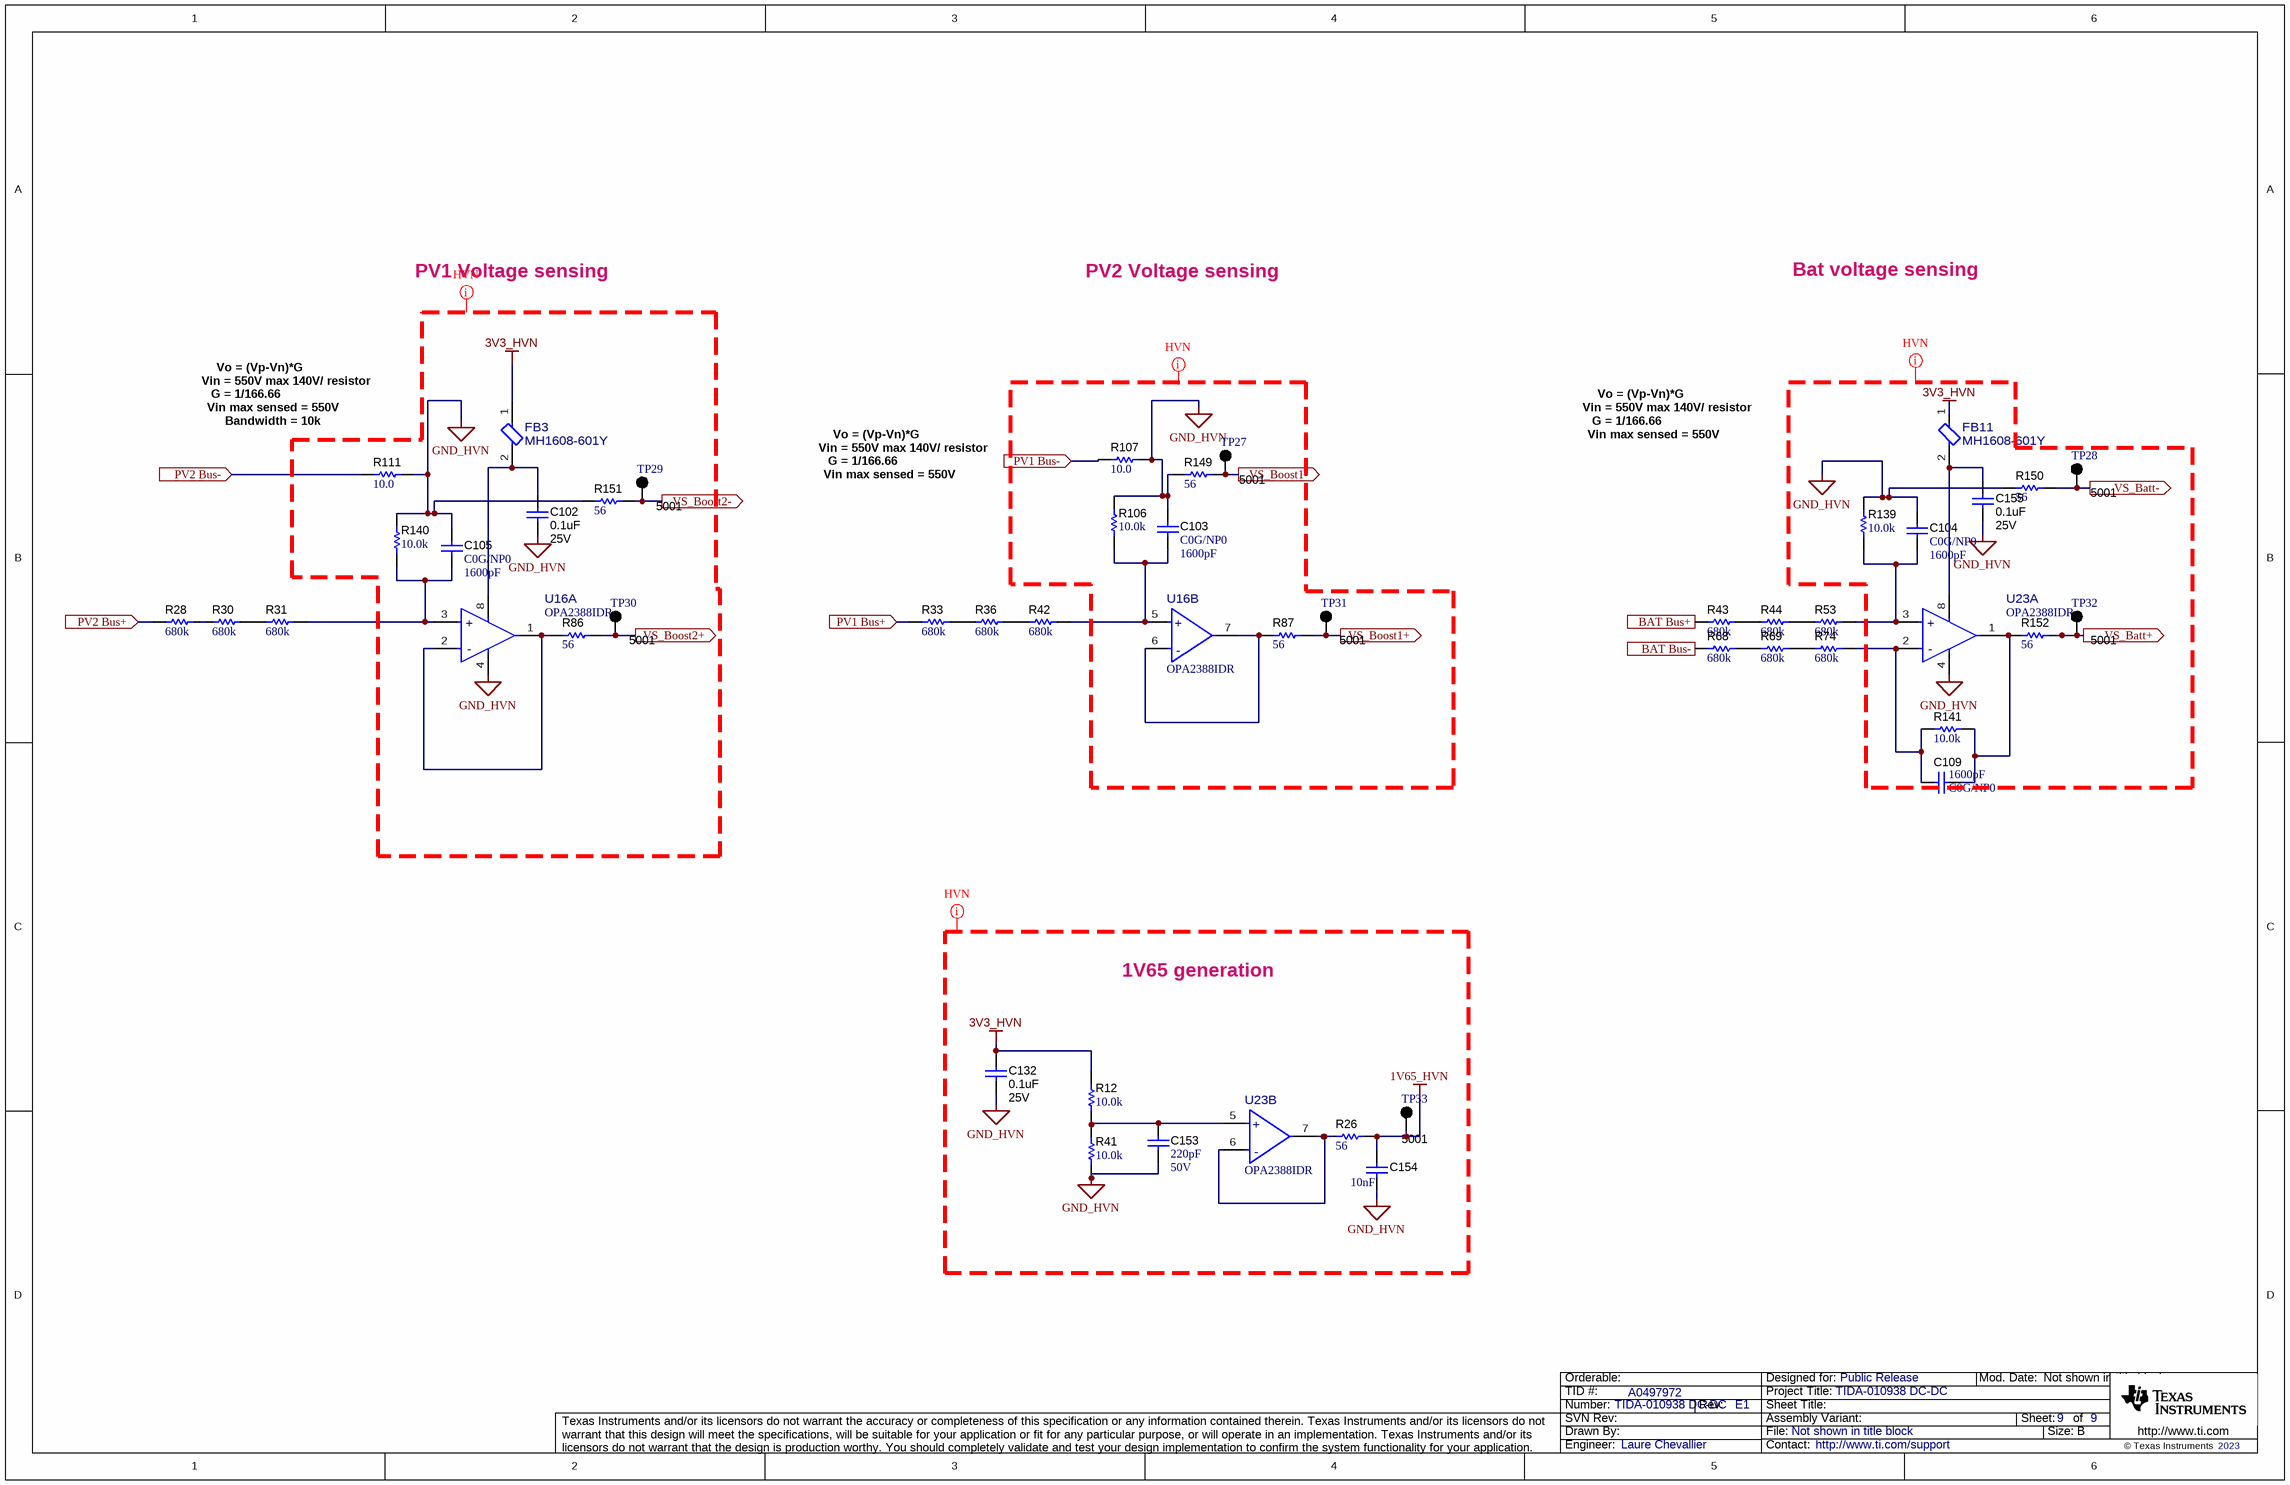
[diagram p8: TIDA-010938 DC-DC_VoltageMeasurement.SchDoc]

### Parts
C102  ValueDisplayed: 0.1uF  VDC_V: 25V  [0603]  (hidden comment: C0603X104K3RACTU)
C103  TempCo: C0G/NP0  ValueDisplayed: 1600pF  [0603]  (hidden comment: GRM1885C1H162JA01D)
C104  TempCo: C0G/NP0  ValueDisplayed: 1600pF  [0603]  (hidden comment: GRM1885C1H162JA01D)
C105  TempCo: C0G/NP0  ValueDisplayed: 1600pF  [0603]  (hidden comment: GRM1885C1H162JA01D)
C109  TempCo: C0G/NP0  ValueDisplayed: 1600pF  [0603]  (hidden comment: GRM1885C1H162JA01D)
C132  ValueDisplayed: 0.1uF  VDC_V: 25V  [0603]  (hidden comment: C0603X104K3RACTU)
C153  Cap_F: 220pF  VDC_V: 50V  [0603]  (hidden comment: GRM188R71H221KA01D)
C154  Cap_F: 10nF  [0603]  (hidden comment: SR0603X7R103K1NT95(F)#M123A)
C155  ValueDisplayed: 0.1uF  VDC_V: 25V  [0603]  (hidden comment: C0603X104K3RACTU)
FB3  MH1608-601Y  [FP-MH1608-601Y_0603-MFG]
FB11  MH1608-601Y  [FP-MH1608-601Y_0603-MFG]
R12  ValueDisplayed: 10.0k  [0603]  (hidden comment: RG1608P-103-B-T5)
R26  ValueDisplayed: 56  [0603]  (hidden comment: RG1608P-560-B-T5)
R28  ValueDisplayed: 680k  [TNPV1206]  (hidden comment: TNPV1206680KBEEN)
R30  ValueDisplayed: 680k  [TNPV1206]  (hidden comment: TNPV1206680KBEEN)
R31  ValueDisplayed: 680k  [TNPV1206]  (hidden comment: TNPV1206680KBEEN)
R33  ValueDisplayed: 680k  [TNPV1206]  (hidden comment: TNPV1206680KBEEN)
R36  ValueDisplayed: 680k  [TNPV1206]  (hidden comment: TNPV1206680KBEEN)
R41  ValueDisplayed: 10.0k  [0603]  (hidden comment: RG1608P-103-B-T5)
R42  ValueDisplayed: 680k  [TNPV1206]  (hidden comment: TNPV1206680KBEEN)
R43  ValueDisplayed: 680k  [TNPV1206]  (hidden comment: TNPV1206680KBEEN)
R44  ValueDisplayed: 680k  [TNPV1206]  (hidden comment: TNPV1206680KBEEN)
R53  ValueDisplayed: 680k  [TNPV1206]  (hidden comment: TNPV1206680KBEEN)
R68  ValueDisplayed: 680k  [TNPV1206]  (hidden comment: TNPV1206680KBEEN)
R69  ValueDisplayed: 680k  [TNPV1206]  (hidden comment: TNPV1206680KBEEN)
R74  ValueDisplayed: 680k  [TNPV1206]  (hidden comment: TNPV1206680KBEEN)
R86  ValueDisplayed: 56  [0603]  (hidden comment: RG1608P-560-B-T5)
R87  ValueDisplayed: 56  [0603]  (hidden comment: RG1608P-560-B-T5)
R106  ValueDisplayed: 10.0k  [0603]  (hidden comment: RG1608P-103-B-T5)
R107  ValueDisplayed: 10.0  [0603]  (hidden comment: RC0603FR-0710RL)
R111  ValueDisplayed: 10.0  [0603]  (hidden comment: RC0603FR-0710RL)
R139  ValueDisplayed: 10.0k  [0603]  (hidden comment: RG1608P-103-B-T5)
R140  ValueDisplayed: 10.0k  [0603]  (hidden comment: RG1608P-103-B-T5)
R141  ValueDisplayed: 10.0k  [0603]  (hidden comment: RG1608P-103-B-T5)
R149  ValueDisplayed: 56  [0603]  (hidden comment: RG1608P-560-B-T5)
R150  ValueDisplayed: 56  [0603]  (hidden comment: RG1608P-560-B-T5)
R151  ValueDisplayed: 56  [0603]  (hidden comment: RG1608P-560-B-T5)
R152  ValueDisplayed: 56  [0603]  (hidden comment: RG1608P-560-B-T5)
TP27  5001  [Keystone5001]
TP28  5001  [Keystone5001]
TP29  5001  [Keystone5001]
TP30  5001  [Keystone5001]
TP31  5001  [Keystone5001]
TP32  5001  [Keystone5001]
TP33  5001  [Keystone5001]
U16  OPA2388IDR  [D0008A-MFG]  (parts A,B of 2)
U23  OPA2388IDR  [D0008A-MFG]  (parts A,B of 2)

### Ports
BAT Bus+ (in), BAT Bus- (in), PV1 Bus+ (in), PV1 Bus- (in), PV2 Bus+ (in), PV2 Bus- (in), VS_Batt+ (out), VS_Batt- (out), VS_Boost1+ (out), VS_Boost1- (out), VS_Boost2+ (out), VS_Boost2- (out)

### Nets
1V65_HVN: C154.1 R26.2 TP33.1
3V3_HVN: C132.2 FB3.1 FB11.1 R12.1
GND_HVN: C102.1 C103.1 C104.1 C105.1 C132.1 C153.1 C154.2 C155.1 R41.2 R106.2 R107.2 R111.2 R139.2 R140.1 R149.1 R150.1 R151.1 U16.4(V-) U23.4(V-)
BAT Bus+: R43.1 ; port BAT Bus+
BAT Bus-: R68.1 ; port BAT Bus-
Boost1_IN-: R107.1 ; port PV1 Bus-
Boost2_IN-: R111.1 ; port PV2 Bus-
PV1 Bus+: R33.1 ; port PV1 Bus+
PV2 Bus+: R28.1 ; port PV2 Bus+
VS_Batt+: R152.2 TP32.1 ; port VS_Batt+
VS_Batt-: R150.2 TP28.1 ; port VS_Batt-
VS_Boost1+: R87.2 TP31.1 ; port VS_Boost1+
VS_Boost1-: R149.2 TP27.1 ; port VS_Boost1-
VS_Boost2+: R86.2 TP30.1 ; port VS_Boost2+
VS_Boost2-: R151.2 TP29.1 ; port VS_Boost2-
NetC102_2: C102.2 FB3.2 U16.8(V+)
NetC103_2: C103.2 R42.2 R106.1 U16.5(+IN_B)
NetC104_2: C104.2 R53.2 R139.1 U23.3(+IN_A)
NetC105_2: C105.2 R31.2 R140.2 U16.3(+IN_A)
NetC109_1: C109.1 R74.2 R141.1 U23.2(-IN_A)
NetC109_2: C109.2 R141.2 R152.1 U23.1(OUT_A)
NetC153_2: C153.2 R12.2 R41.1 U23.5(+IN_B)
NetC155_2: C155.2 FB11.2 U23.8(V+)
NetR26_1: R26.1 U23.6(-IN_B) U23.7(OUT_B)
NetR28_2: R28.2 R30.1
NetR30_2: R30.2 R31.1
NetR33_2: R33.2 R36.1
NetR36_2: R36.2 R42.1
NetR43_2: R43.2 R44.1
NetR44_2: R44.2 R53.1
NetR68_2: R68.2 R69.1
NetR69_2: R69.2 R74.1
NetR86_1: R86.1 U16.1(OUT_A) U16.2(-IN_A)
NetR87_1: R87.1 U16.6(-IN_B) U16.7(OUT_B)

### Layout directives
net class HVN: 1V65_HVN, 3V3_HVN, GND_HVN

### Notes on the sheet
- PV1 Voltage sensing
- PV2 Voltage sensing
- Bat voltage sensing
- Vo = (Vp-Vn)*G
- G = 1/166.66
- Vin max sensed = 550V
- Bandwidth = 10k
- Vin = 550V max 140V/ resistor
- 1V65 generation

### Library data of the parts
C102 C132 C155 = CMP-0006979-5: CAP, CERM, 0.1 uF, 25 V, +/- 10%, X7R, 0603; Manufacturer: Kemet; Polarized: N; Value: 0.1uF; U/M: EA; Cap_F: 100nF; Value1: Unknown; TaMin_C: -55°C; TaMax_C: 125°C; AEC Category: Q200; SizeArea_mm2: 1.28; SizeAreaWB_mm2: 4.68; SizeX_mm: 1.6; SizeY_mm: 0.8; SizeZ_mm: 1
C103-C105 C109 = CMP-0007189-4: CAP, CERM, 1600 pF, 50 V, +/- 5%, C0G/NP0, 0603; Manufacturer: MuRata; TaMin_C: -55°C; Polarized: N; SizeAreaWB_mm2: 4.68; Value1: Unknown; U/M: EA; Value: 1600pF; TaMax_C: 125°C; SizeZ_mm: 1; SizeX_mm: 1.6; SizeY_mm: 0.8; Value2: 50V; SizeArea_mm2: 1.28; Cap_F: 1.6nF; AEC Category: Q200
C153 = CMP-0007442-5: as C11 on sheet TIDA-010938 bidirectional DC-DC_Interleaved1
C154 = CMP-0079721-1: CAP, CERM, 0.01 µF, 25 V,+/- 10%, X7R, 0603; Manufacturer: Presidio Components; TaMin_C: -55°C; Polarized: N; SizeAreaWB_mm2: 4.68; U/M: EA; Value: 0.01uF; TaMax_C: 125°C; SizeZ_mm: 1; SizeX_mm: 1.6; SizeY_mm: 0.8; Value2: 25V; SizeArea_mm2: 1.28; AEC Category: Q200; ValueDisplayed: 0.01µF
FB3 FB11 = CMP-0037505-1: as FB4 on sheet TIDA-010938 bidirectional DC-DC_Interleaved1
R12 R41 R106 R139-R141 = CMP-0023404-3: as R39 on sheet TIDA-010938 bidirectional DC-DC_Interleaved1
R26 R86 R87 R149-R152 = CMP-0023572-3: as R3-R5 on sheet TIDA-010938 bidirectional DC-DC_Interleaved1
R28 R30 R31 R33 R36 R42-R44 R53 R68 R69 R74 = CMP-0018816-2: RES, 680 k, 0.1%, 1 W, 1206; Manufacturer: Vishay Draloric; Power_W: 1W; TempCo: 25 ppm/C; U/M: EA; Value: 680k; SizeX_mm: 3.2; SizeY_mm: 1.6; SizeZ_mm: 0.65; SizeArea_mm2: 5.12; AEC Qualified: N; VDC_V: 700V; AEC Category: Q200
R107 R111 = CMP-0022751-4: RES, 10.0, 1%, 0.1 W, 0603; Manufacturer: Yageo; Power_W: 100mW; TempCo: 100 ppm/C; Value_Code: 10R0; Value: 10.0; EIA_Code: E96; Res_ohm: 10; SizeX_mm: 1.6; SizeY_mm: 0.8; SizeZ_mm: 1; Value2: 0.1W; SizeArea_mm2: 1.28; AEC Qualified: N; VDC_V: 75V; AEC Category: Q200; SizeAreaWB_mm2: 4.68
TP27-TP33 = CMP-0055138-2: as TP1-TP3 on sheet TIDA-010938 bidirectional DC-DC_Interleaved1
U16 U23 = CMP-0097119-1: Precision, Zero-Drift, Zero-Crossover, True Rail-to-Rail, Input/Output Operational Amplifiers; Manufacturer: Texas Instruments; TJmax_C: +150°C; TaMin_C: -55°C; AEC Qualified: No; Max Dual Supply Voltage: 2.75V; Min Dual Supply Voltage: 1.25V; Input Offset Voltage: 0.00025mV; Output Current Per Channel: 30-60mA; Standoff Height: 0.11mm; Number Of Channels: 2; Min Supply Voltage: 2.5V; Input Bias Current: 0.00003uA; Nominal Supply Current: 1.7-1.9mA; Voltage Gain: 126-148dB; Bandwidth: 10MHz; SizeZ_mm: 1.75mm; Max Supply Voltage: 5.5V; Response Time: 0.75-2us

## Sheet TIDA-010938 DC-DC_Data conditionning.SchDoc
size 431 x 279 mm; Date: Not shown in title block; ApprovedBy: Not shown in title block; CheckedBy: Not shown in title block; Author: Not shown in title block; CompanyName: Not shown in title block; Engineer: Not shown in title block; Organization: Not shown in title block; Address1: Not shown in title block; Address2: Not shown in title block; Address3: Not shown in title block; Address4: Not shown in title block; DocumentNumber: 1; Revision: Use project parameter SCH_Rev; SheetNumber: 7; SheetTotal: 9; PageSetup: Record=PageOptions¦CenterHorizontal=True¦CenterVertical=True¦PrintScale=1.00¦XCorrection=1.00¦YCorrection=1.00¦PrintKind=0¦BorderSize=5000000¦LeftOffset=0¦BottomOffset=0¦Orientation=2¦PaperLength=1000¦PaperWidth=1000¦Scale=100¦PaperSource=15¦PrintQuality=600¦MediaType=1¦DitherType=10¦PaperKind=Letter¦PrintScaleMode=1
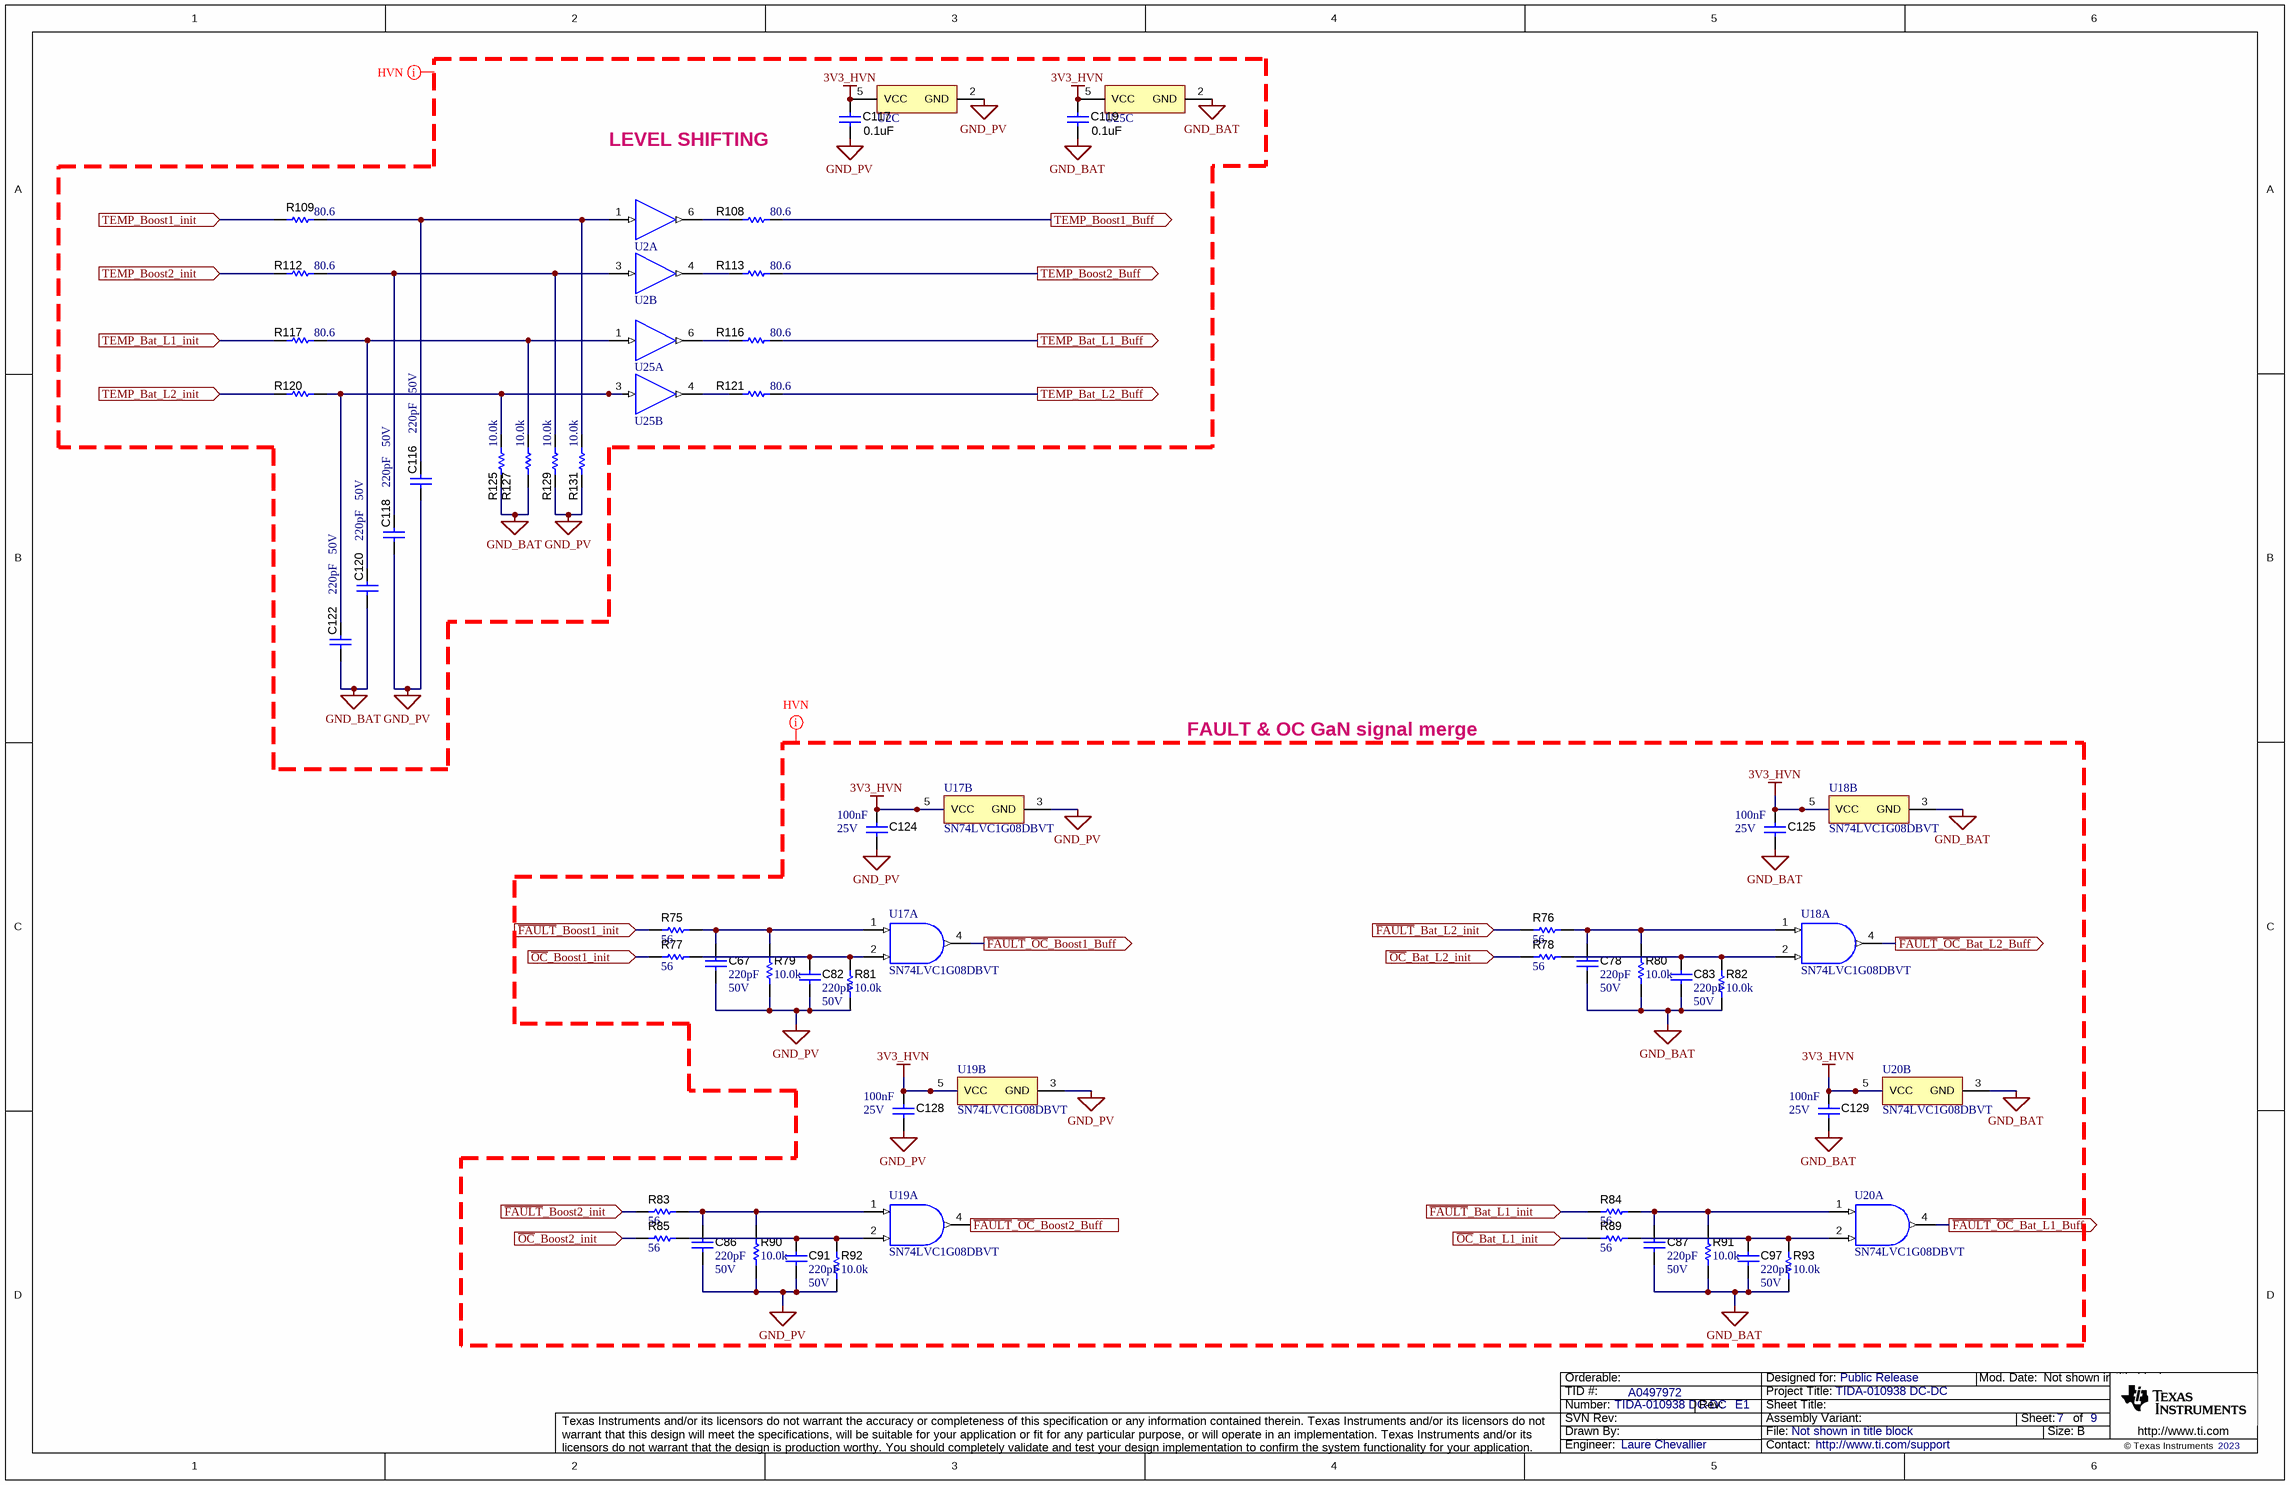
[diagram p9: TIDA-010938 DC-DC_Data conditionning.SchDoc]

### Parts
C67  Cap_F: 220pF  VDC_V: 50V  [0603]  (hidden comment: GRM188R71H221KA01D)
C78  Cap_F: 220pF  VDC_V: 50V  [0603]  (hidden comment: GRM188R71H221KA01D)
C82  Cap_F: 220pF  VDC_V: 50V  [0603]  (hidden comment: GRM188R71H221KA01D)
C83  Cap_F: 220pF  VDC_V: 50V  [0603]  (hidden comment: GRM188R71H221KA01D)
C86  Cap_F: 220pF  VDC_V: 50V  [0603]  (hidden comment: GRM188R71H221KA01D)
C87  Cap_F: 220pF  VDC_V: 50V  [0603]  (hidden comment: GRM188R71H221KA01D)
C91  Cap_F: 220pF  VDC_V: 50V  [0603]  (hidden comment: GRM188R71H221KA01D)
C97  Cap_F: 220pF  VDC_V: 50V  [0603]  (hidden comment: GRM188R71H221KA01D)
C116  Cap_F: 220pF  VDC_V: 50V  [0603]  (hidden comment: GRM188R71H221KA01D)
C117  ValueDisplayed: 0.1uF  [0603]  (hidden comment: 885012206095)
C118  Cap_F: 220pF  VDC_V: 50V  [0603]  (hidden comment: GRM188R71H221KA01D)
C119  ValueDisplayed: 0.1uF  [0603]  (hidden comment: 885012206095)
C120  Cap_F: 220pF  VDC_V: 50V  [0603]  (hidden comment: GRM188R71H221KA01D)
C122  Cap_F: 220pF  VDC_V: 50V  [0603]  (hidden comment: GRM188R71H221KA01D)
C124  Cap_F: 100nF  VDC_V: 25V  [0603]  (hidden comment: 06033C104JAT2A)
C125  Cap_F: 100nF  VDC_V: 25V  [0603]  (hidden comment: 06033C104JAT2A)
C128  Cap_F: 100nF  VDC_V: 25V  [0603]  (hidden comment: 06033C104JAT2A)
C129  Cap_F: 100nF  VDC_V: 25V  [0603]  (hidden comment: 06033C104JAT2A)
R75  ValueDisplayed: 56  [0603]  (hidden comment: RG1608P-560-B-T5)
R76  ValueDisplayed: 56  [0603]  (hidden comment: RG1608P-560-B-T5)
R77  ValueDisplayed: 56  [0603]  (hidden comment: RG1608P-560-B-T5)
R78  ValueDisplayed: 56  [0603]  (hidden comment: RG1608P-560-B-T5)
R79  ValueDisplayed: 10.0k  [0603]  (hidden comment: RG1608P-103-B-T5)
R80  ValueDisplayed: 10.0k  [0603]  (hidden comment: RG1608P-103-B-T5)
R81  ValueDisplayed: 10.0k  [0603]  (hidden comment: RG1608P-103-B-T5)
R82  ValueDisplayed: 10.0k  [0603]  (hidden comment: RG1608P-103-B-T5)
R83  ValueDisplayed: 56  [0603]  (hidden comment: RG1608P-560-B-T5)
R84  ValueDisplayed: 56  [0603]  (hidden comment: RG1608P-560-B-T5)
R85  ValueDisplayed: 56  [0603]  (hidden comment: RG1608P-560-B-T5)
R89  ValueDisplayed: 56  [0603]  (hidden comment: RG1608P-560-B-T5)
R90  ValueDisplayed: 10.0k  [0603]  (hidden comment: RG1608P-103-B-T5)
R91  ValueDisplayed: 10.0k  [0603]  (hidden comment: RG1608P-103-B-T5)
R92  ValueDisplayed: 10.0k  [0603]  (hidden comment: RG1608P-103-B-T5)
R93  ValueDisplayed: 10.0k  [0603]  (hidden comment: RG1608P-103-B-T5)
R108  ValueDisplayed: 80.6  [0603]  (hidden comment: RC0603FR-0780R6L)
R109  ValueDisplayed: 80.6  [0603]  (hidden comment: RC0603FR-0780R6L)
R112  ValueDisplayed: 80.6  [0603]  (hidden comment: RC0603FR-0780R6L)
R113  ValueDisplayed: 80.6  [0603]  (hidden comment: RC0603FR-0780R6L)
R116  ValueDisplayed: 80.6  [0603]  (hidden comment: RC0603FR-0780R6L)
R117  ValueDisplayed: 80.6  [0603]  (hidden comment: RC0603FR-0780R6L)
R120  RC0603FR-0780R6L  [0603]  (value not drawn)
R121  ValueDisplayed: 80.6  [0603]  (hidden comment: RC0603FR-0780R6L)
R125  ValueDisplayed: 10.0k  [0603]  (hidden comment: RG1608P-103-B-T5)
R127  ValueDisplayed: 10.0k  [0603]  (hidden comment: RG1608P-103-B-T5)
R129  ValueDisplayed: 10.0k  [0603]  (hidden comment: RG1608P-103-B-T5)
R131  ValueDisplayed: 10.0k  [0603]  (hidden comment: RG1608P-103-B-T5)
U2  SN74LVC2G34DBVR  [DBV0006A_N]  (value not drawn)  (parts A,B,C of 3)
U17  SN74LVC1G08DBVT  [DBV0005A_N]  (parts A,B of 2)
U18  SN74LVC1G08DBVT  [DBV0005A_N]  (parts A,B of 2)
U19  SN74LVC1G08DBVT  [DBV0005A_N]  (parts A,B of 2)
U20  SN74LVC1G08DBVT  [DBV0005A_N]  (parts A,B of 2)
U25  SN74LVC2G34DBVR  [DBV0006A_N]  (value not drawn)  (parts A,B,C of 3)

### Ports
TEMP_Bat_L1_Buff (out), TEMP_Bat_L1_init (in), TEMP_Bat_L2_Buff (out), TEMP_Bat_L2_init (in), TEMP_Boost1_Buff (out), TEMP_Boost1_init (in), TEMP_Boost2_Buff (out), TEMP_Boost2_init (in), ~{FAULT}_Bat_L1_init (in), ~{FAULT}_Bat_L2_init (in), ~{FAULT}_Boost1_init (in), ~{FAULT}_Boost2_init (in), ~{FAULT}_~{OC}_Bat_L1_Buff (out), ~{FAULT}_~{OC}_Bat_L2_Buff (out), ~{FAULT}_~{OC}_Boost1_Buff (out), ~{FAULT}_~{OC}_Boost2_Buff (out), ~{OC}_Bat_L1_init (in), ~{OC}_Bat_L2_init (in), ~{OC}_Boost1_init (in), ~{OC}_Boost2_init (in)

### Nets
3V3_HVN: C117.1 C119.1 C124.1 C125.1 C128.1 C129.1 U2.5(VCC) U17.5(VCC) U18.5(VCC) U19.5(VCC) U20.5(VCC) U25.5(VCC)
GND_BAT: C78.1 C83.1 C87.1 C97.1 C119.2 C120.1 C122.1 C125.2 C129.2 R80.1 R82.1 R91.1 R93.1 R125.1 R127.1 U18.3(GND) U20.3(GND) U25.2(GND)
GND_PV: C67.1 C82.1 C86.1 C91.1 C116.1 C117.2 C118.1 C124.2 C128.2 R79.1 R81.1 R90.1 R92.1 R129.1 R131.1 U2.2(GND) U17.3(GND) U19.3(GND)  [project net DC_Bus-]
~{FAULT}_Bat_L1_init: R84.1 ; port ~{FAULT}_Bat_L1_init
~{FAULT}_Bat_L2_init: R76.1 ; port ~{FAULT}_Bat_L2_init
~{FAULT}_Boost1_init: R75.1 ; port ~{FAULT}_Boost1_init
~{FAULT}_Boost2_init: R83.1 ; port ~{FAULT}_Boost2_init
~{FAULT}_~{OC}_Bat_L1_Buff: U20.4(Y) ; port ~{FAULT}_~{OC}_Bat_L1_Buff
~{FAULT}_~{OC}_Bat_L2_Buff: U18.4(Y) ; port ~{FAULT}_~{OC}_Bat_L2_Buff
~{FAULT}_~{OC}_Boost1_Buff: U17.4(Y) ; port ~{FAULT}_~{OC}_Boost1_Buff
~{FAULT}_~{OC}_Boost2_Buff: U19.4(Y) ; port ~{FAULT}_~{OC}_Boost2_Buff
~{OC}_Bat_L1_init: R89.1 ; port ~{OC}_Bat_L1_init
~{OC}_Bat_L2_init: R78.1 ; port ~{OC}_Bat_L2_init
~{OC}_Boost1_init: R77.1 ; port ~{OC}_Boost1_init
~{OC}_Boost2_init: R85.1 ; port ~{OC}_Boost2_init
TEMP_Bat_L1_Buff: R116.2 ; port TEMP_Bat_L1_Buff
TEMP_Bat_L1_init: R117.1 ; port TEMP_Bat_L1_init
TEMP_Bat_L2_Buff: R121.2 ; port TEMP_Bat_L2_Buff
TEMP_Bat_L2_init: R120.1 ; port TEMP_Bat_L2_init
TEMP_Boost1_Buff: R108.2 ; port TEMP_Boost1_Buff
TEMP_Boost1_init: R109.1 ; port TEMP_Boost1_init
TEMP_Boost2_Buff: R113.2 ; port TEMP_Boost2_Buff
TEMP_Boost2_init: R112.1 ; port TEMP_Boost2_init
NetC67_2: C67.2 R75.2 R79.2 U17.1(A)
NetC78_2: C78.2 R76.2 R80.2 U18.1(A)
NetC82_2: C82.2 R77.2 R81.2 U17.2(B)
NetC83_2: C83.2 R78.2 R82.2 U18.2(B)
NetC86_2: C86.2 R83.2 R90.2 U19.1(A)
NetC87_2: C87.2 R84.2 R91.2 U20.1(A)
NetC91_2: C91.2 R85.2 R92.2 U19.2(B)
NetC97_2: C97.2 R89.2 R93.2 U20.2(B)
NetC116_2: C116.2 R109.2 R131.2 U2.1(1A)
NetC118_2: C118.2 R112.2 R129.2 U2.3(2A)
NetC120_2: C120.2 R117.2 R127.2 U25.1(1A)
NetC122_2: C122.2 R120.2 R125.2 U25.3(2A)
NetR108_1: R108.1 U2.6(1Y)
NetR113_1: R113.1 U2.4(2Y)
NetR116_1: R116.1 U25.6(1Y)
NetR121_1: R121.1 U25.4(2Y)

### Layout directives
net class HVN: 3V3_HVN, GND_BAT, GND_PV

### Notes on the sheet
- LEVEL SHIFTING
- FAULT & OC GaN signal merge

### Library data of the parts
C67 C78 C82 C83 C86 C87 C91 C97 C116 C118 C120 C122 = CMP-0007442-5: as C11 on sheet TIDA-010938 bidirectional DC-DC_Interleaved1
C117 C119 = CMP-0006837-4: as C43 on sheet TIDA-010938 bidirectional DC-DC_Interleaved1
C124 C125 C128 C129 = CMP-0006752-5: as C36 on sheet TIDA-010938 bidirectional DC-DC_Interleaved1
R75-R78 R83-R85 R89 = CMP-0023572-3: as R3-R5 on sheet TIDA-010938 bidirectional DC-DC_Interleaved1
R79-R82 R90-R93 R125 R127 R129 R131 = CMP-0023404-3: as R39 on sheet TIDA-010938 bidirectional DC-DC_Interleaved1
R108 R109 R112 R113 R116 R117 R120 R121 = CMP-0023286-5: RES, 80.6, 1%, 0.1 W, 0603; Manufacturer: Yageo; Power_W: 100mW; TempCo: 100 ppm/C; Value_Code: 80R6; Value: 80.6; EIA_Code: E96; SizeX_mm: 1.6; SizeY_mm: 0.8; SizeZ_mm: 1; Value2: 0.1W; SizeArea_mm2: 1.28; AEC Qualified: N; VDC_V: 75V; AEC Category: Q200; SizeAreaWB_mm2: 4.68
U2 U25 = CMP-0051910-1: Dual Buffer Gate, DBV0006A, LARGE T&R; Manufacturer: Texas Instruments; Logic: True; F @ Nom Voltage(Max)(Mhz): 150; Output Type: CMOS; Output Drive (IOL/IOH)(Max)(mA): 32/-32; Voltage(Nom)(V): 1.8,2.5,3.3,5; 3-State Output: No; VCC(Max)(V): 5.5; ICC @ Nom Voltage(Max)(mA): 0.01; Technology Family: LVC; Input Type: CMOS/TTL; VCC(Min)(V): 1.65; Bits(#): 2; tpd @ Nom Voltage(Max)(ns): 8.6,4.4,4.1,3.2; Rating: Catalog; Sub-Family: Non-Inverting Buffer/Driver
U17-U20 = CMP-0051571-2: as U8 on sheet TIDA-010938 bidirectional DC-DC_Interleaved1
